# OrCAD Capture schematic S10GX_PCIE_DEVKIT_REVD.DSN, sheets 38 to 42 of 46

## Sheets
38 Power - VCCRAM: size C
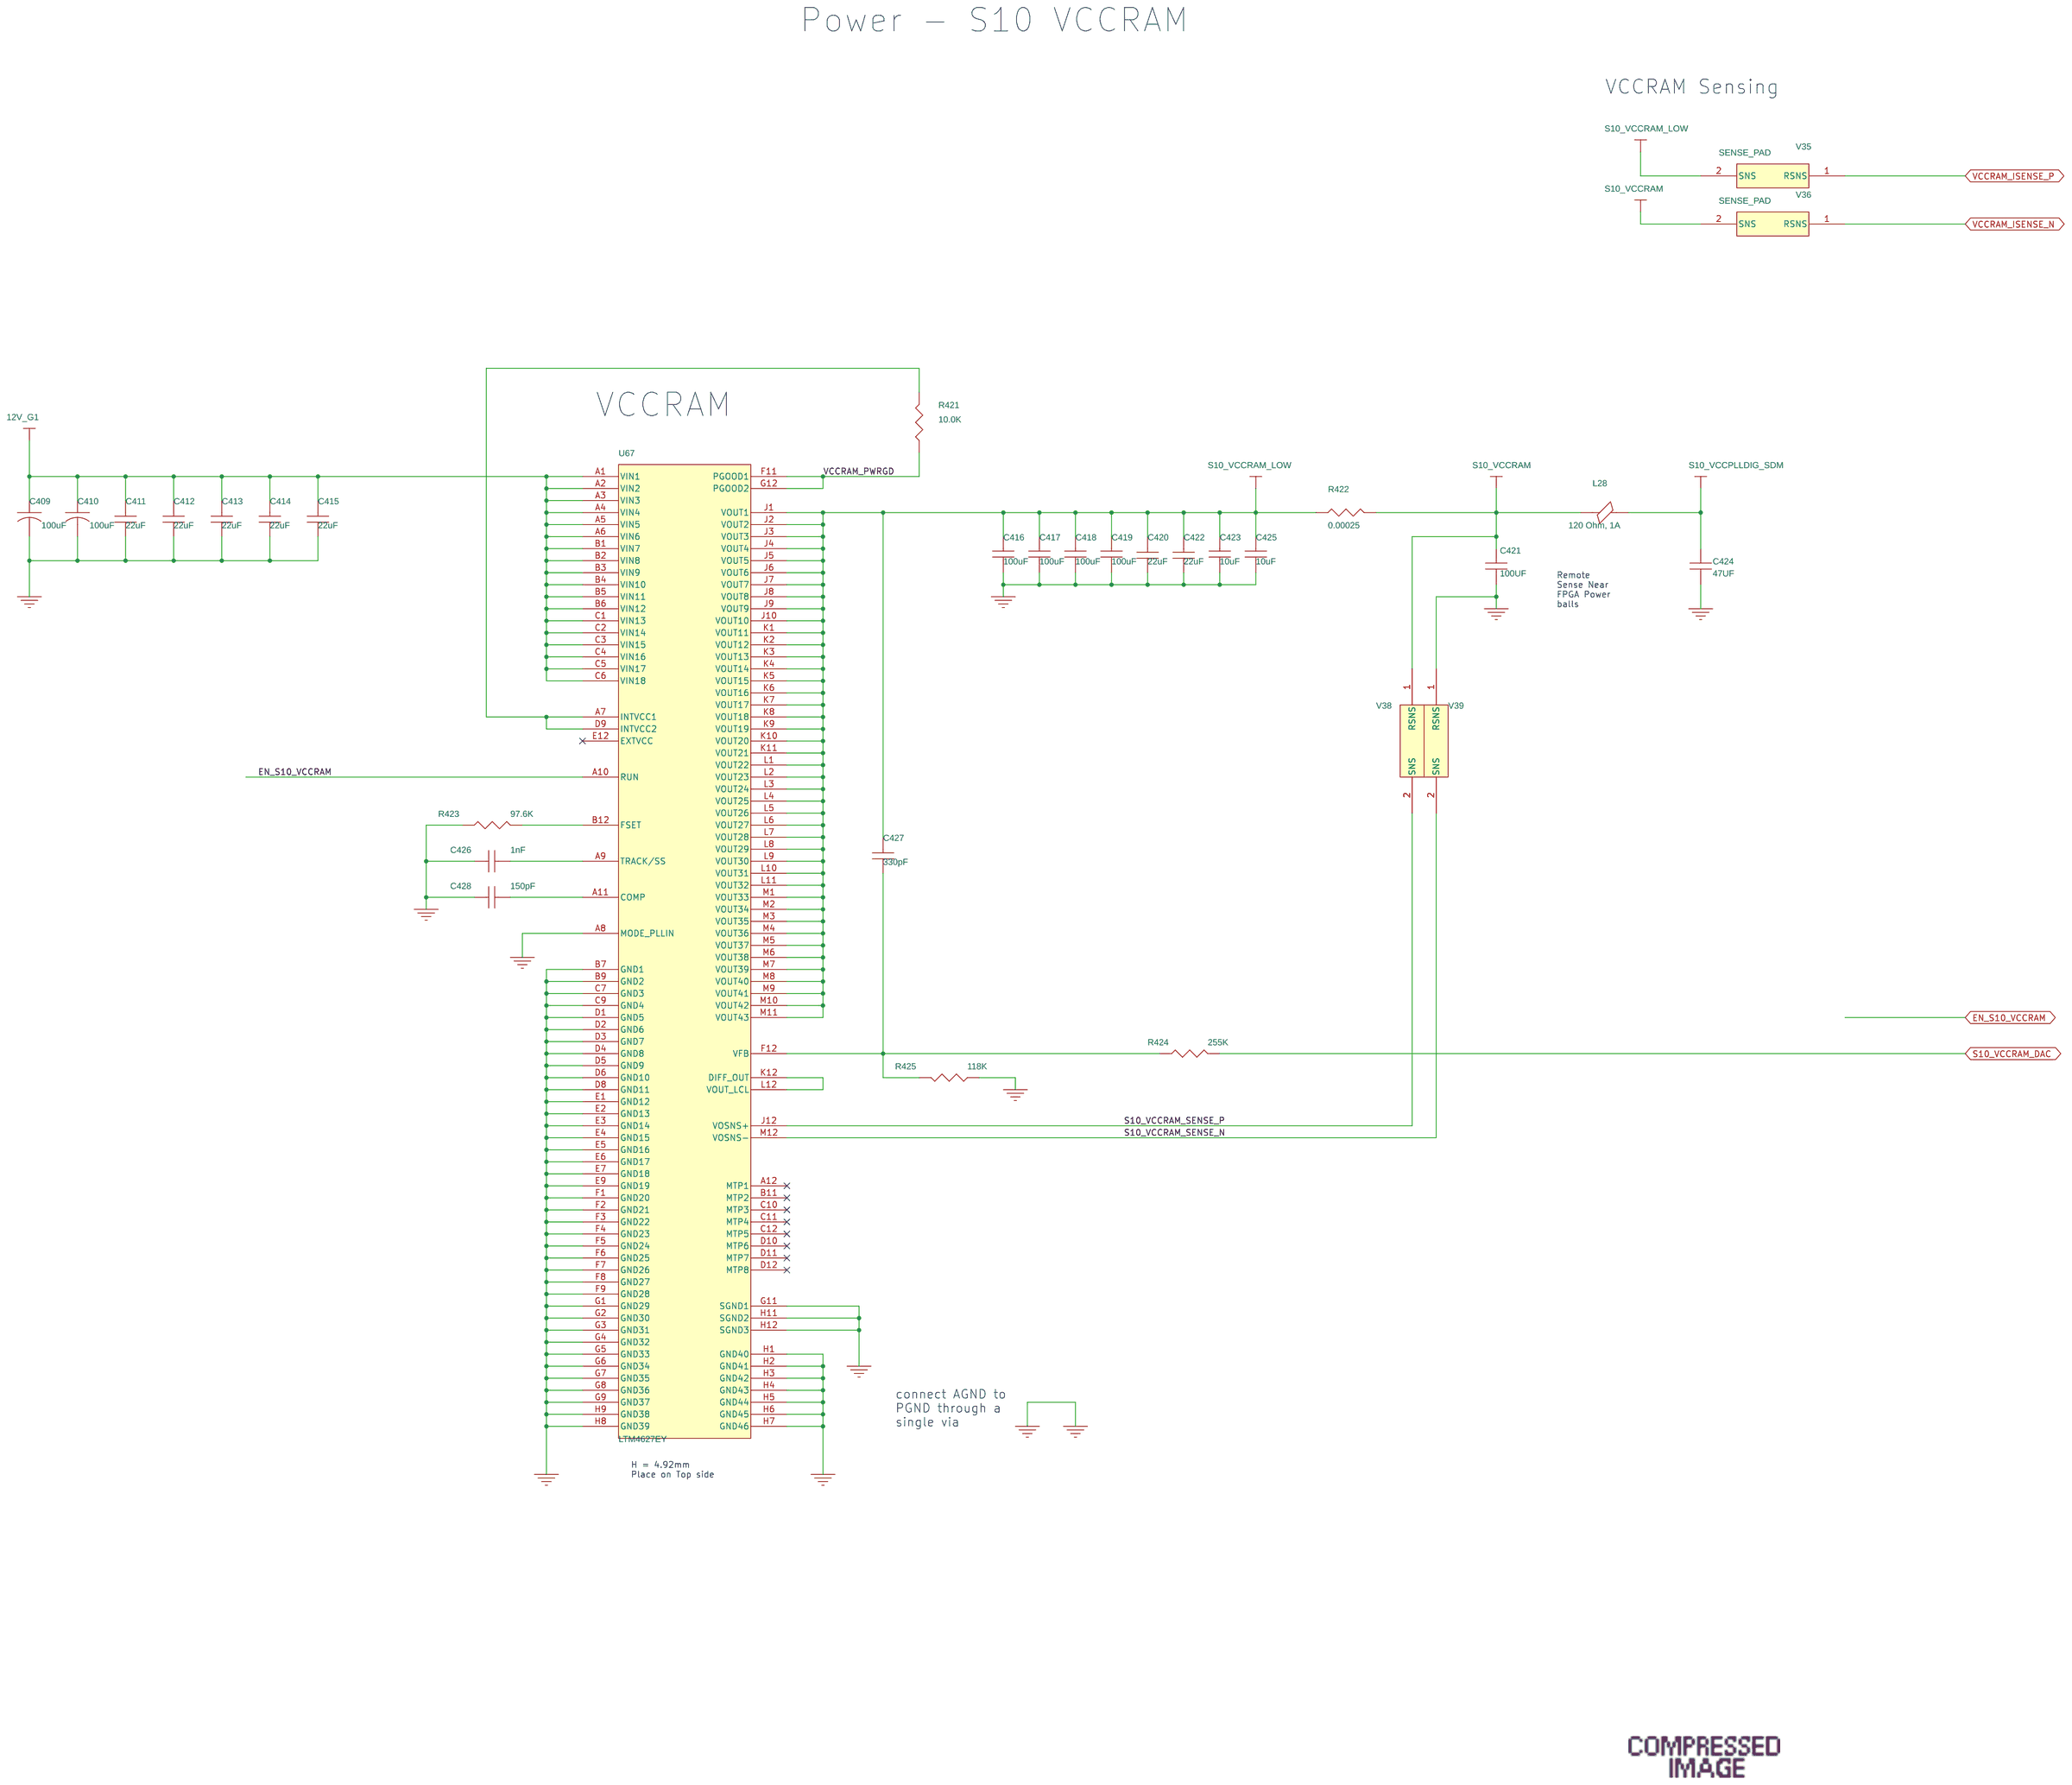
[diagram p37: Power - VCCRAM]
39 Power - VCCPT & 1.8V: size C
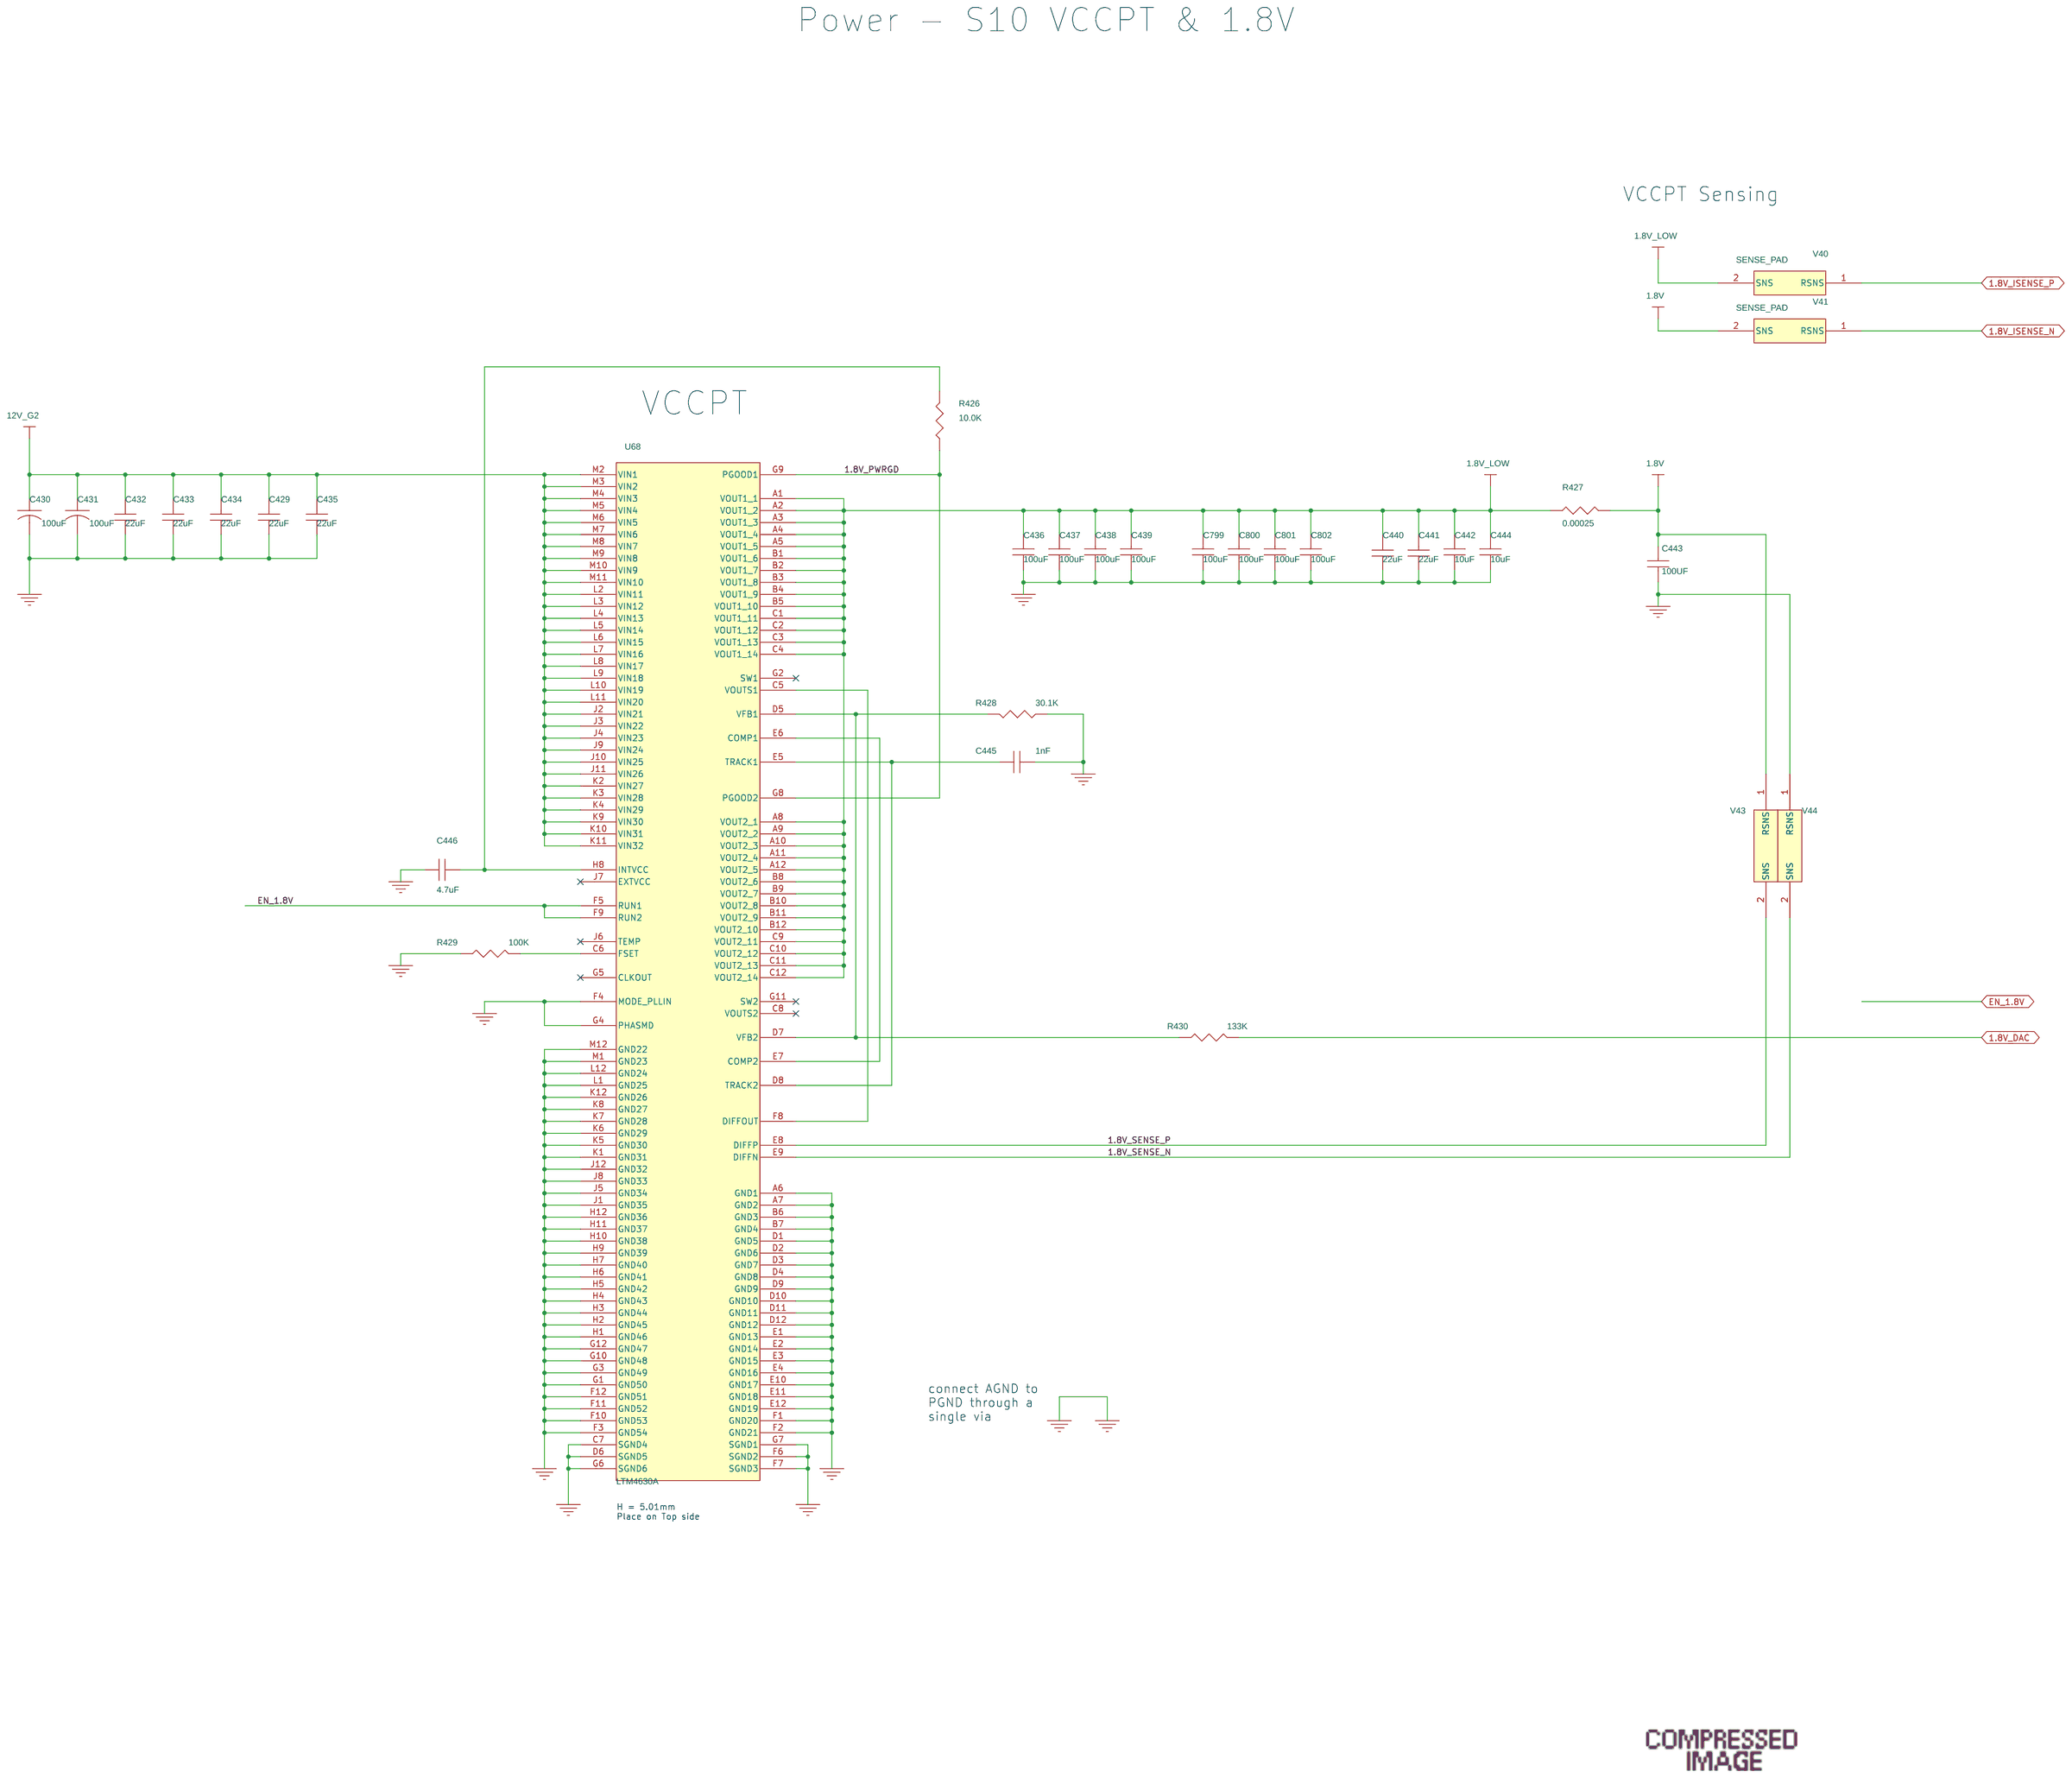
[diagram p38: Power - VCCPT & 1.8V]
40 Power - VCCR_GXB, VCCT_GXB: size C
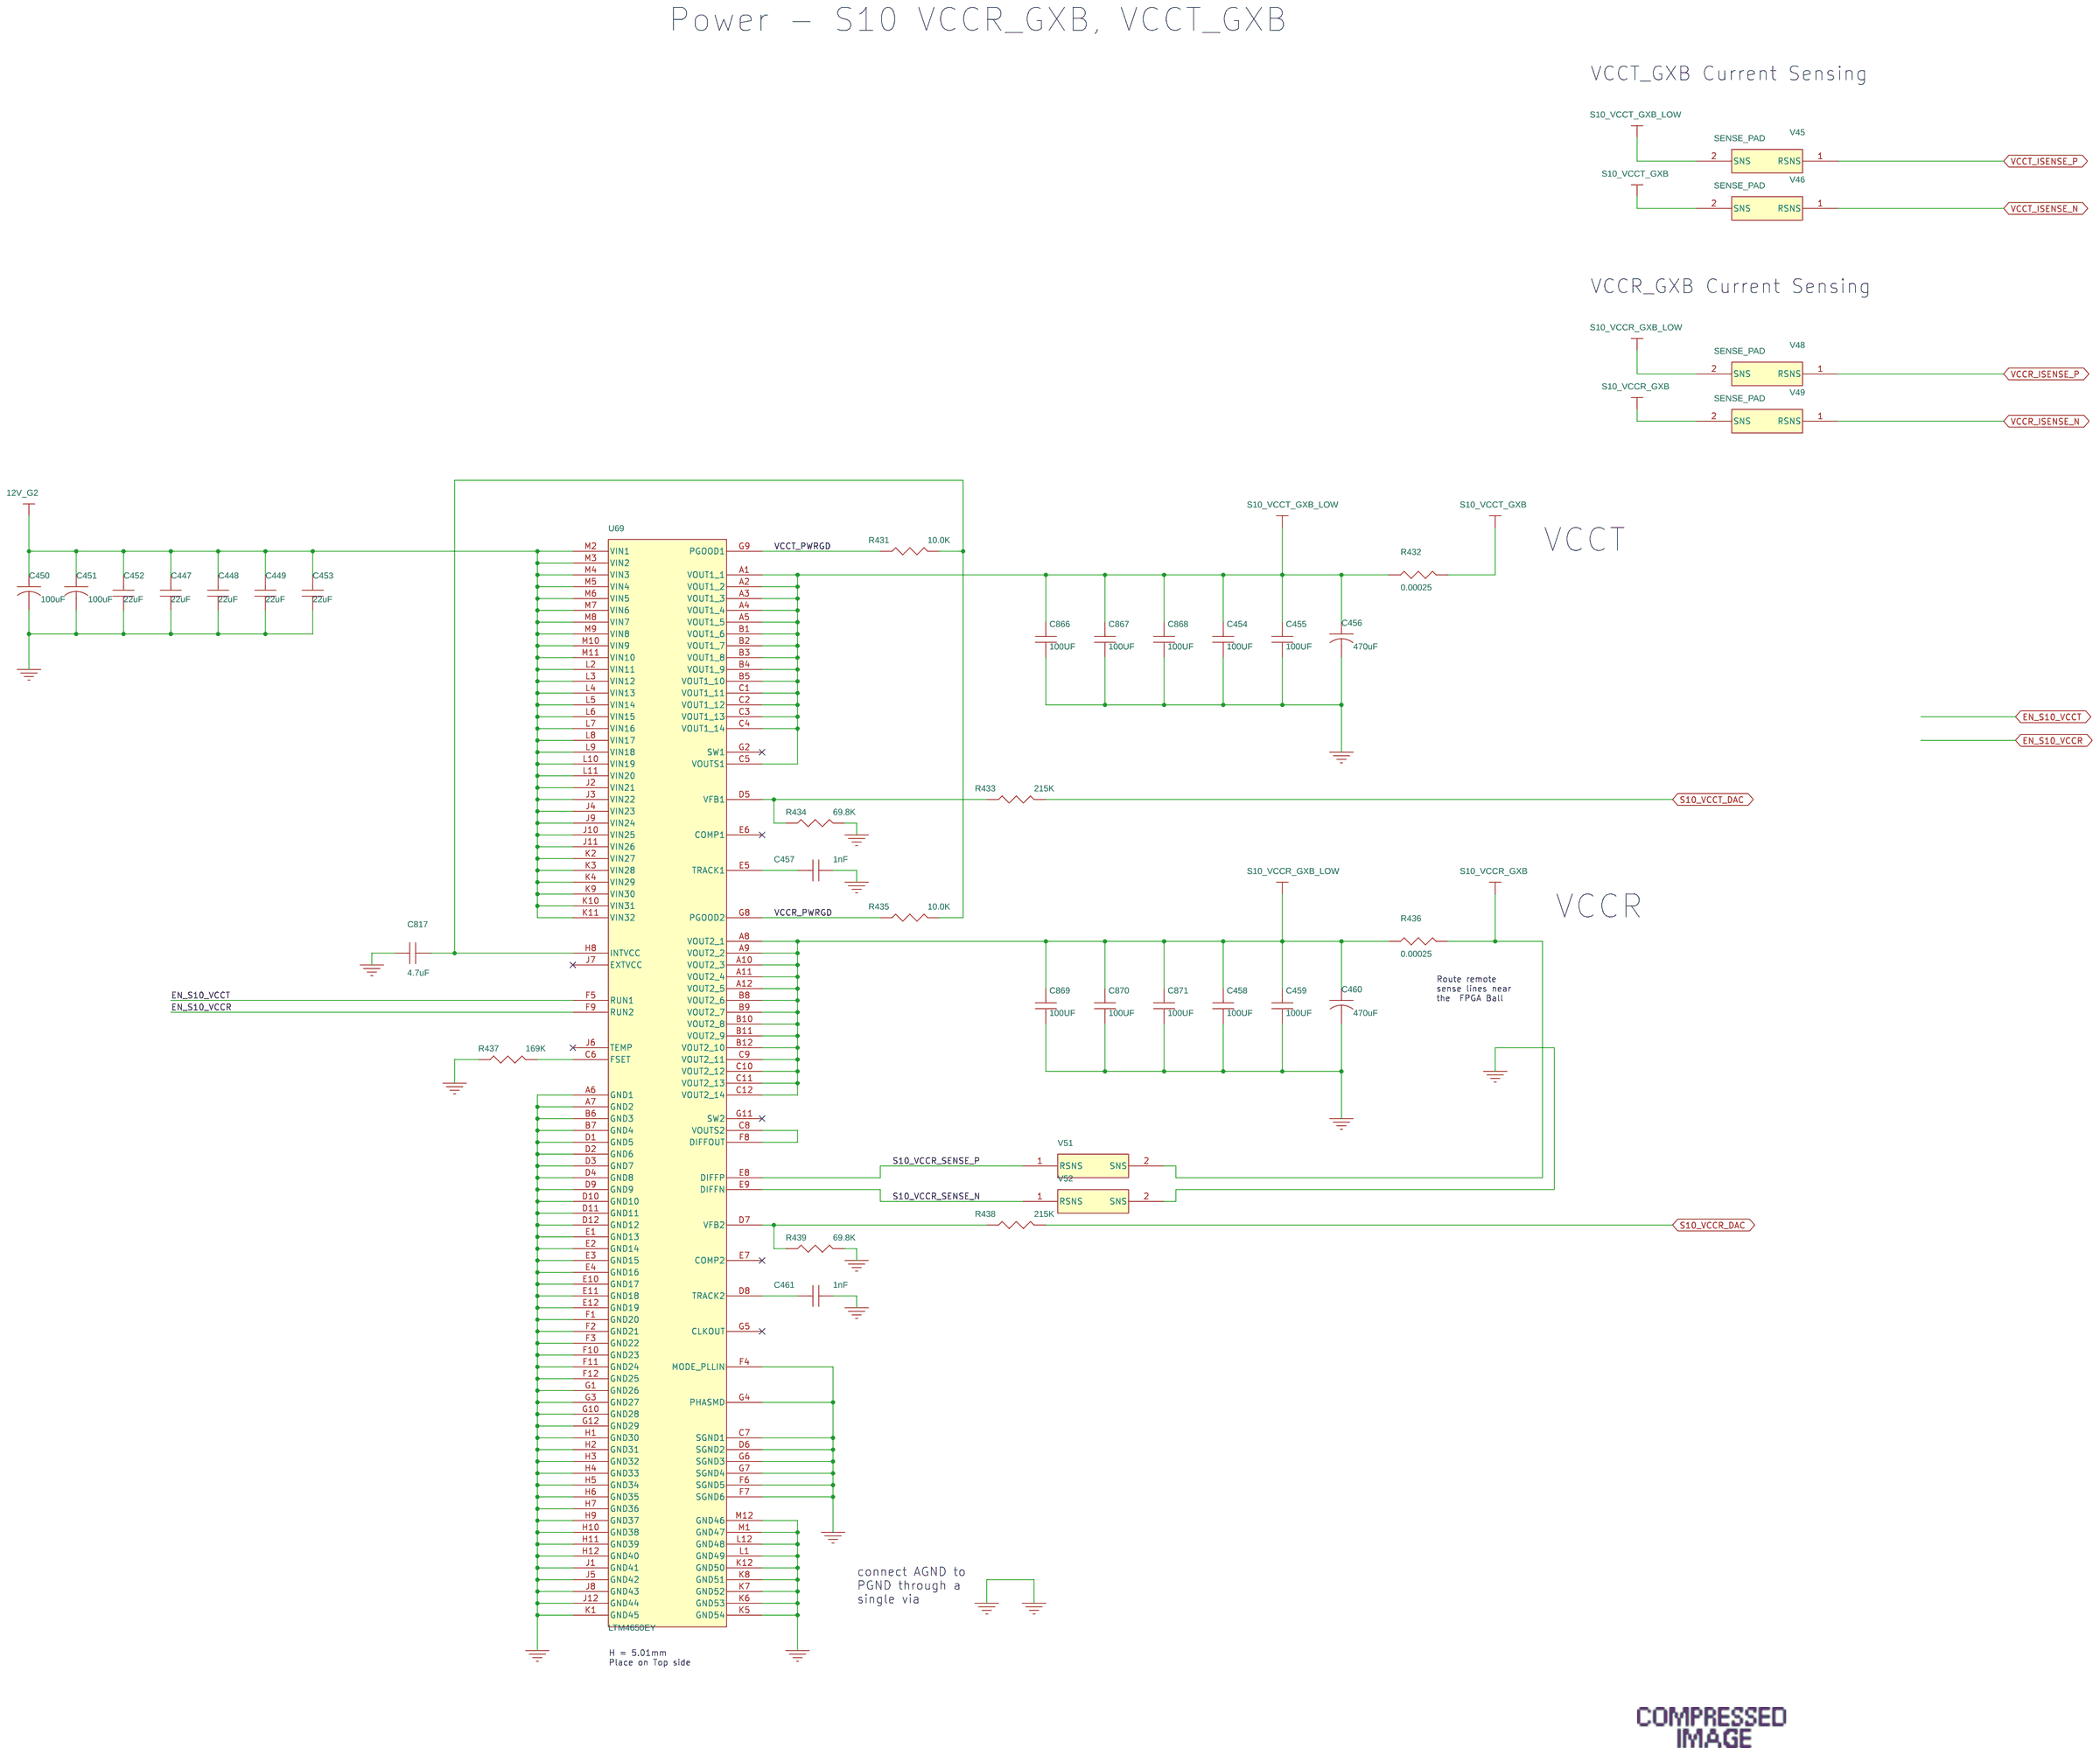
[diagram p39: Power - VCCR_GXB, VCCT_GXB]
41 Power - FMC: size C
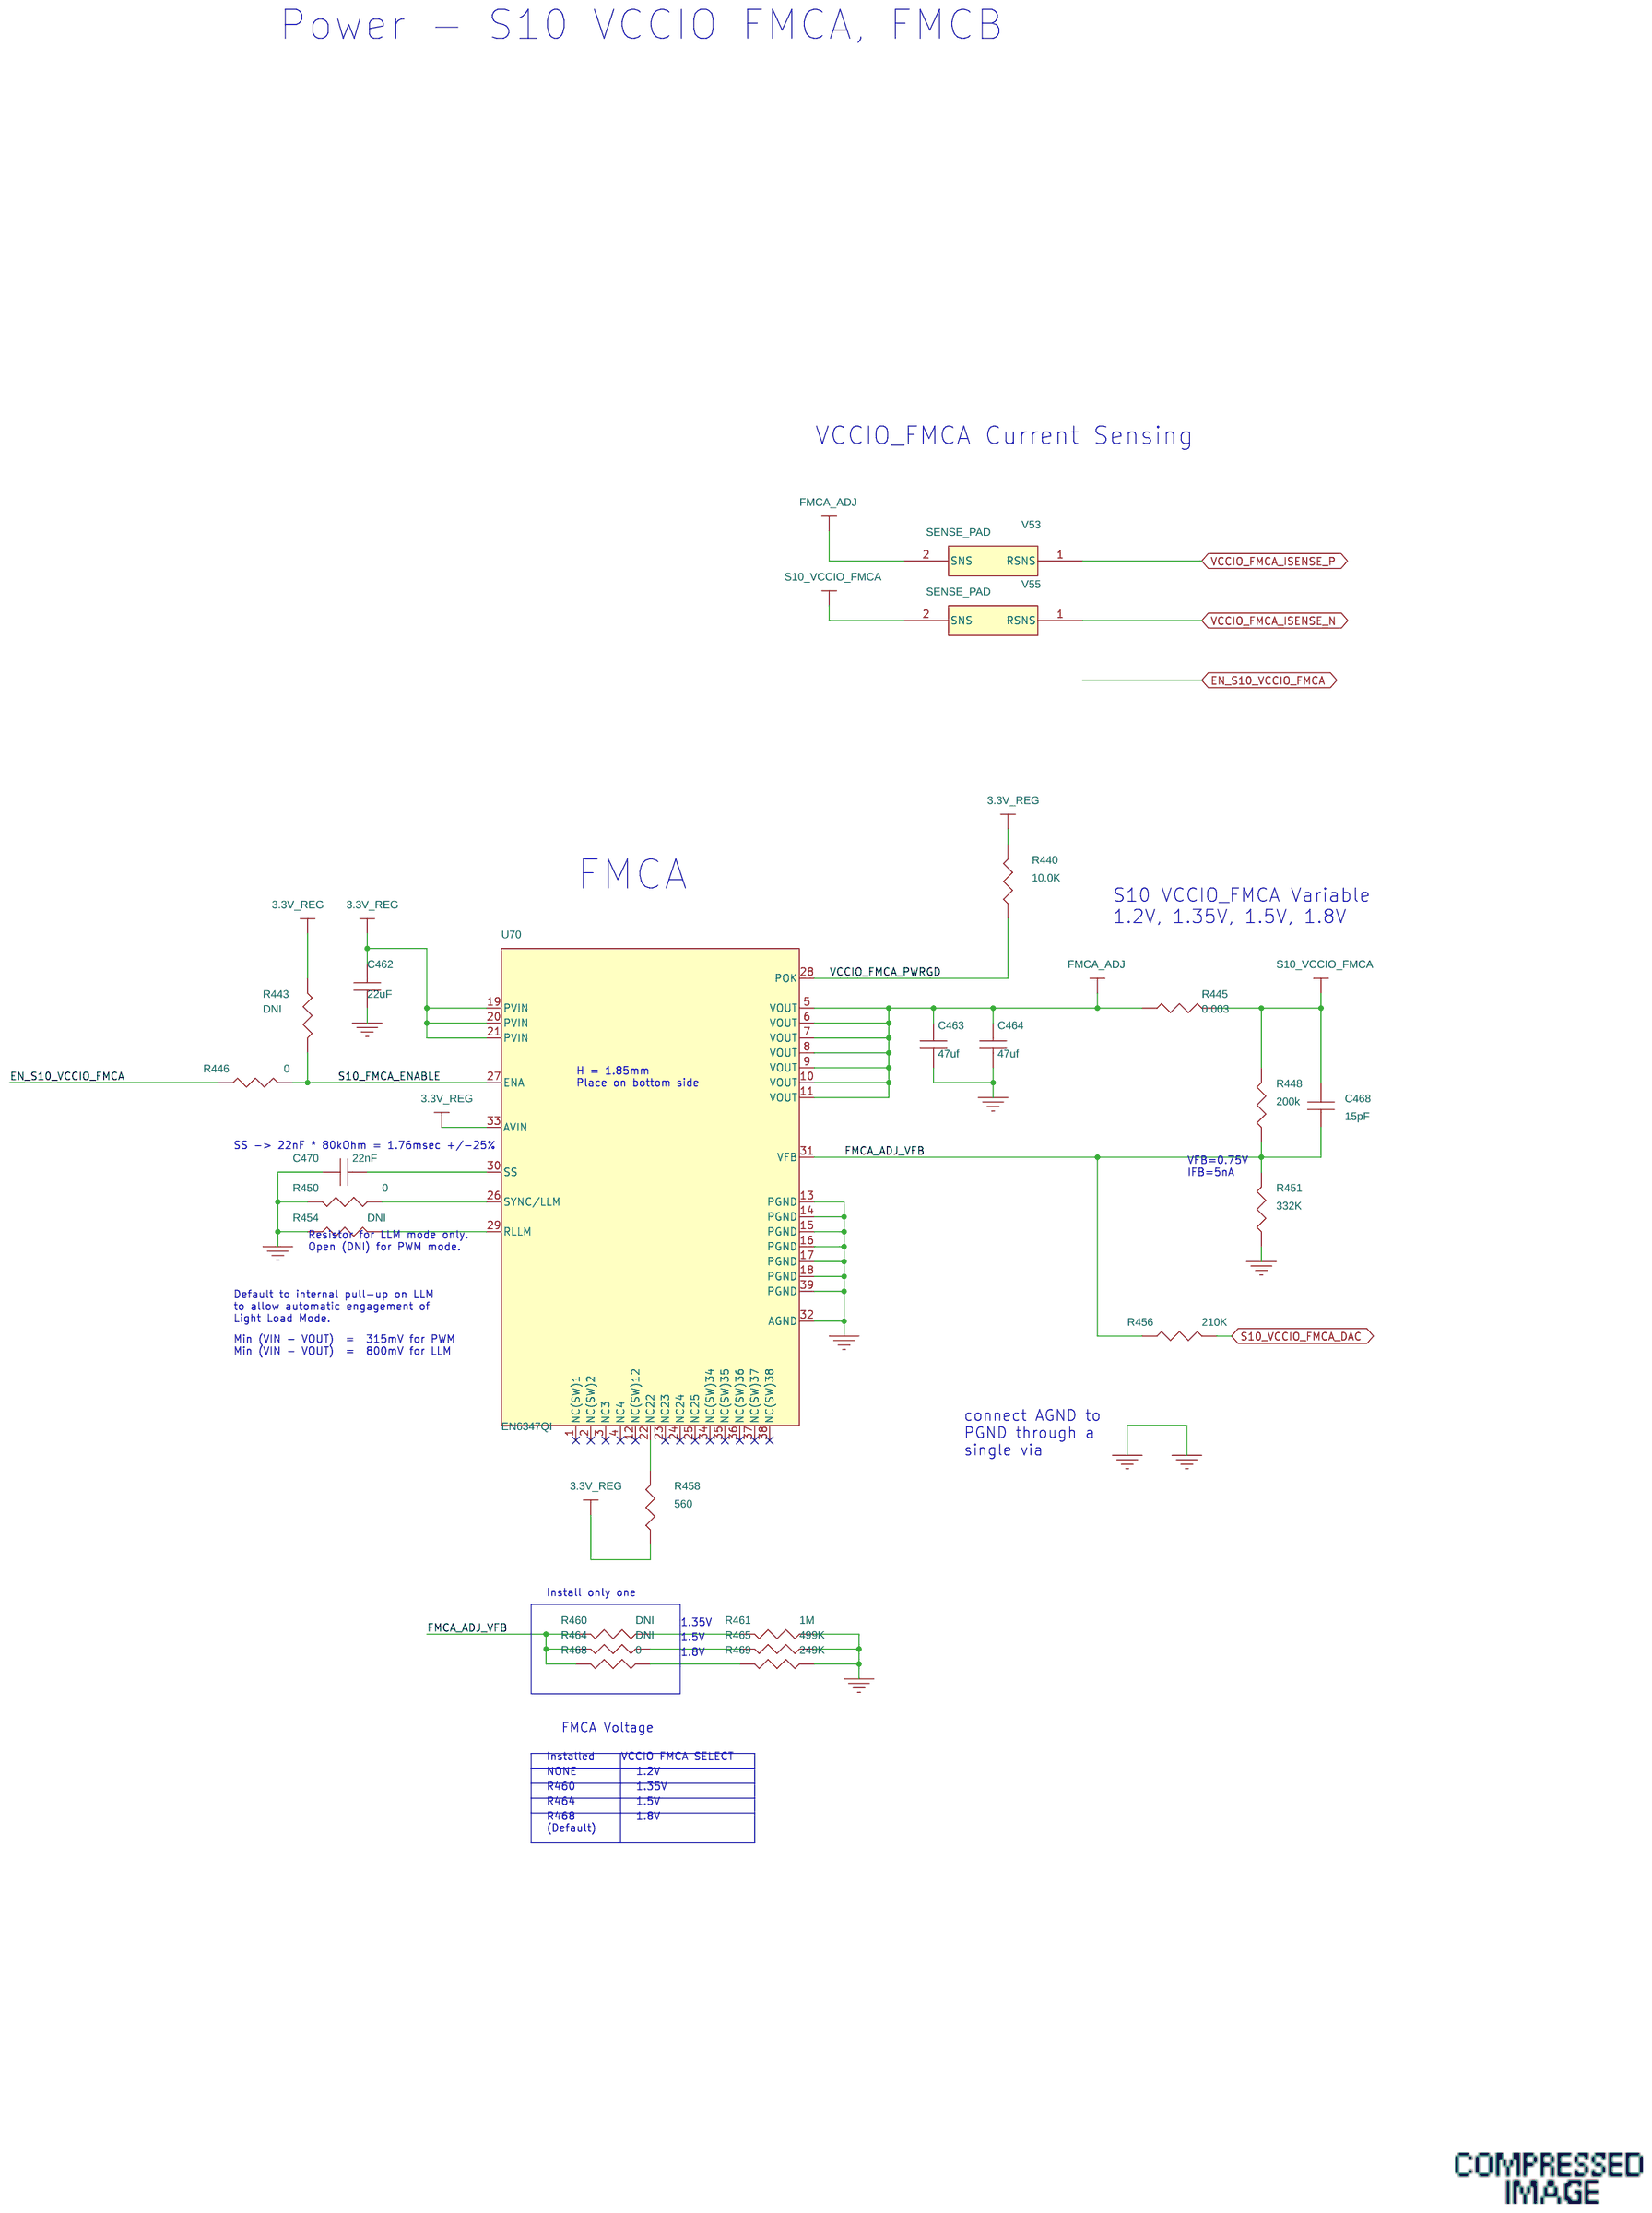
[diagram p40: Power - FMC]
42 Power - HILO MEMORY: size C
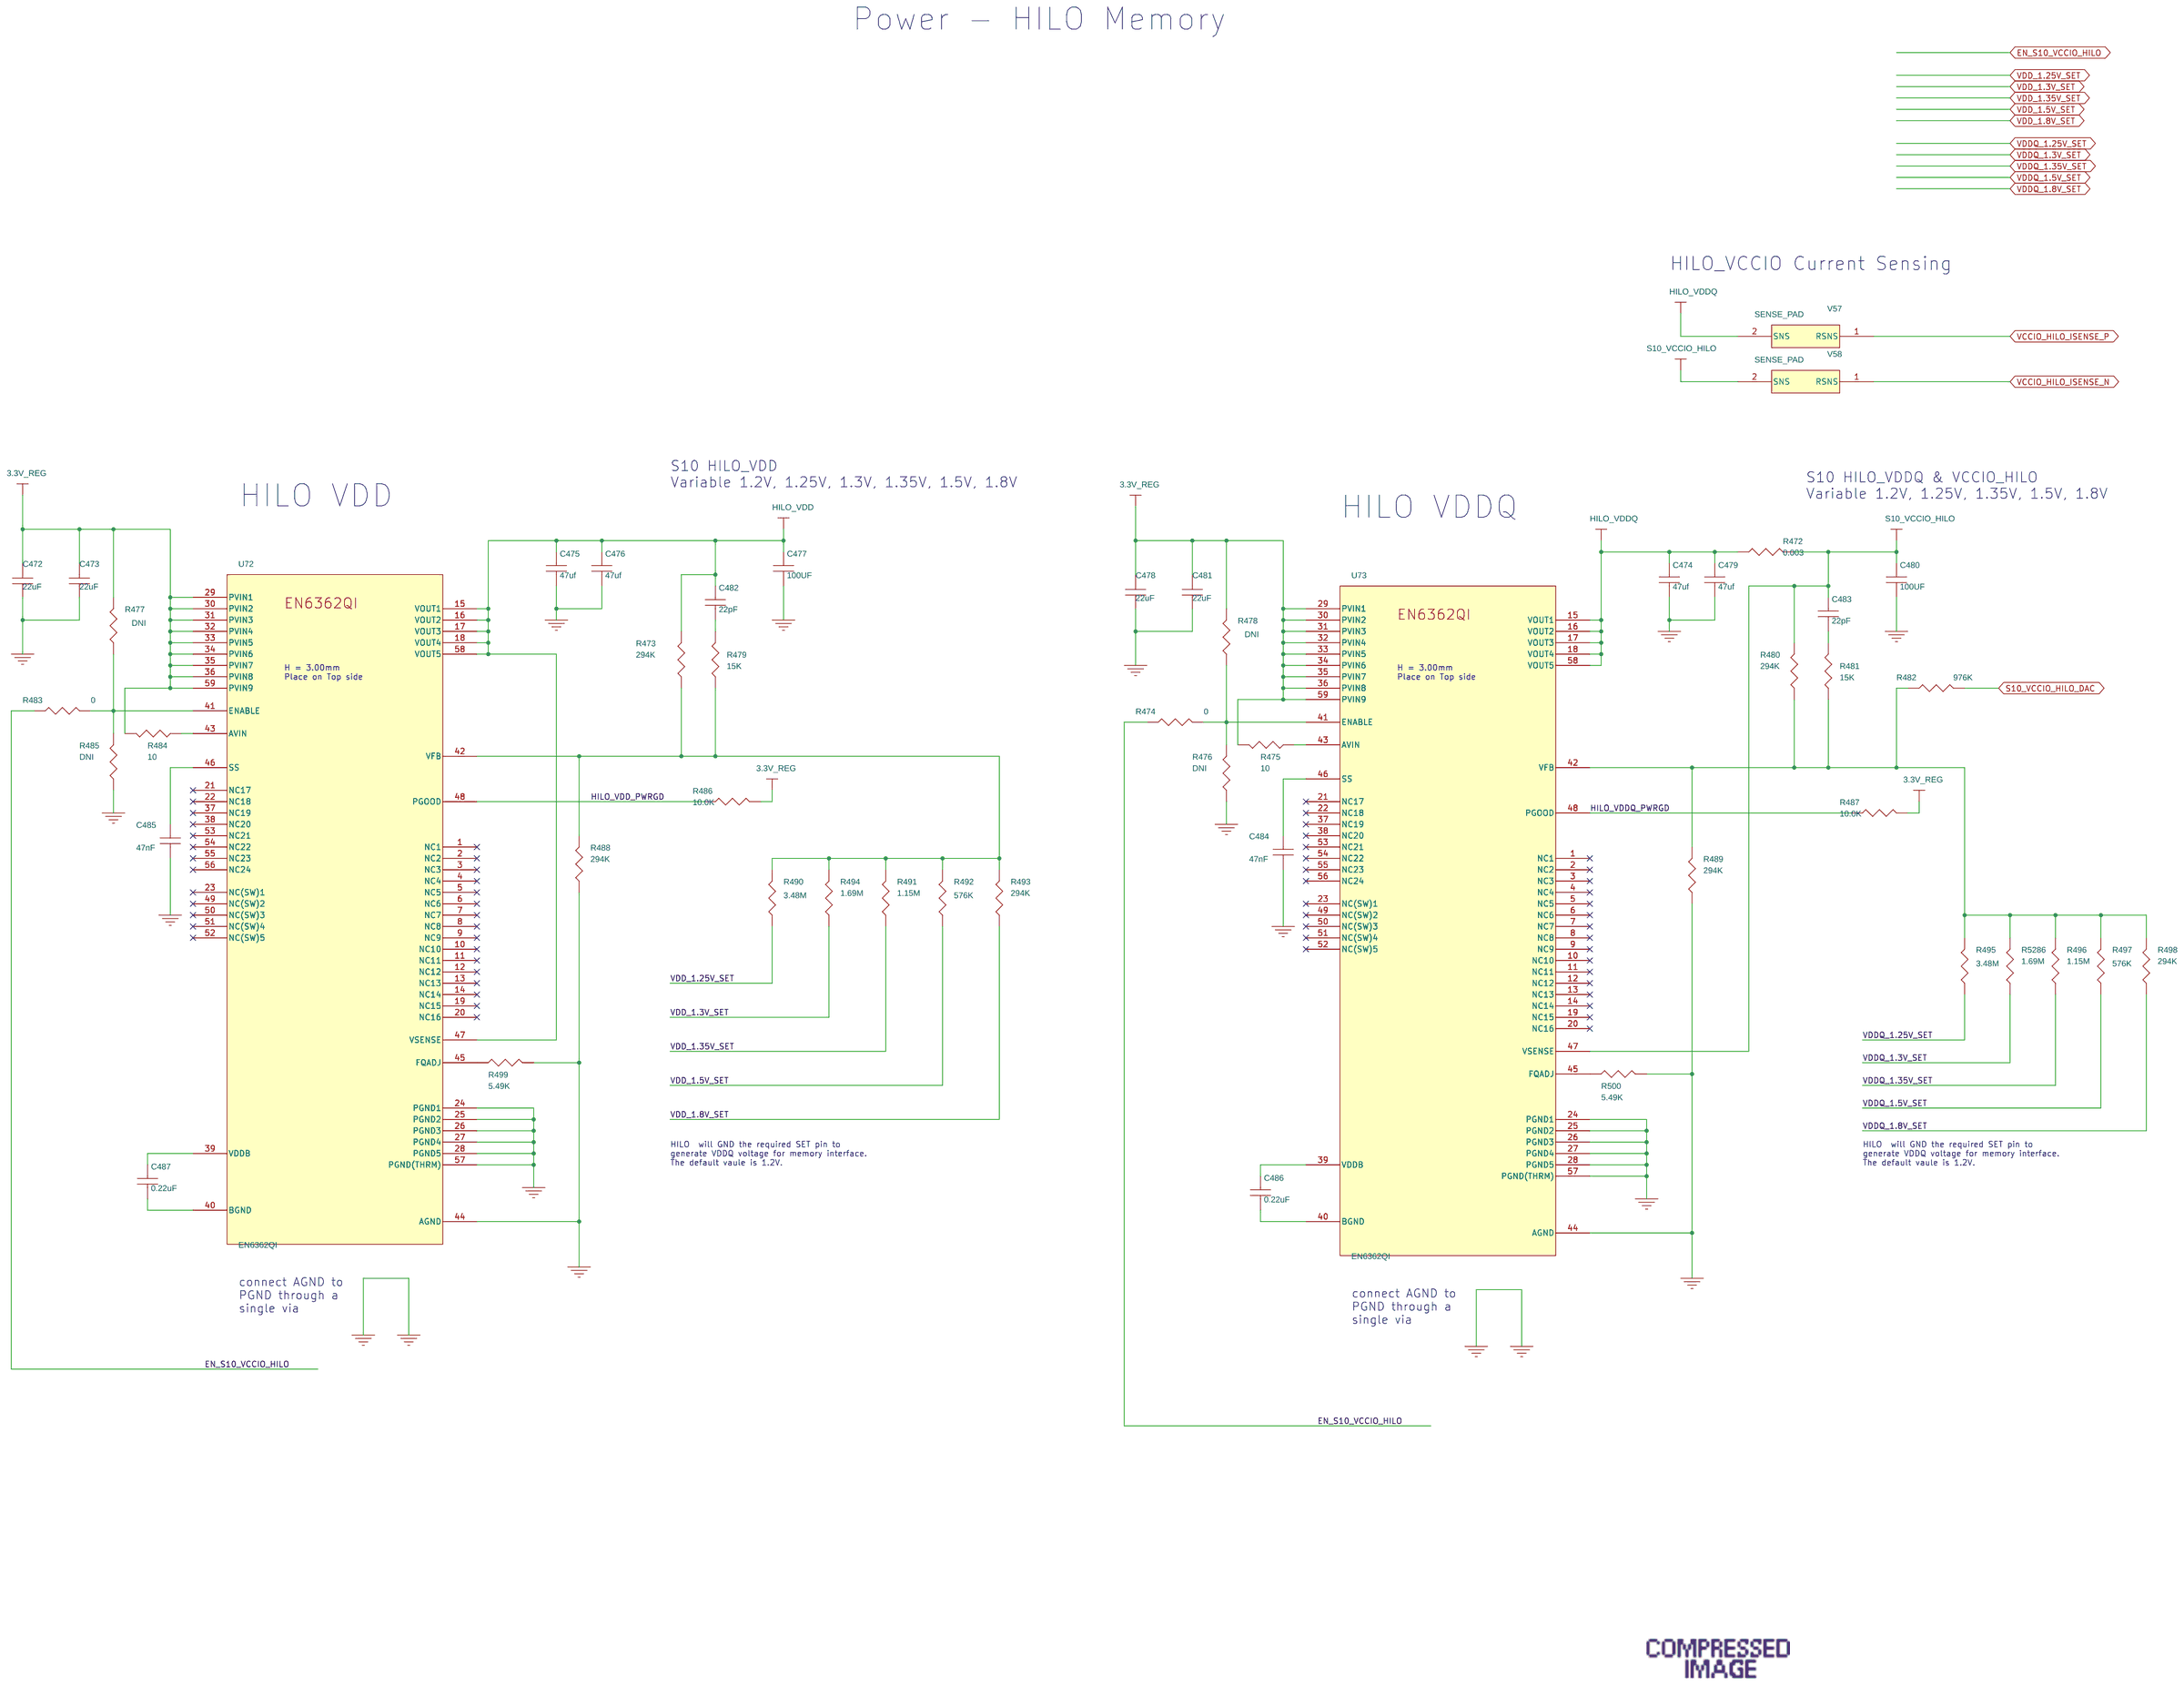
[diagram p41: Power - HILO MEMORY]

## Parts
sheet Power - FMC
C462  22uF  [1206]
C463  47uf  [1206]
C464  47uf  [1206]
C468  15pF  [0402]
C470  22nF  [0402]
R440  10.0K  [0402]
R443  DNI  [0402]
R445  0.003  [WSL2010]
R446  0  [0402]
R448  200k  [0402]
R450  0  [0402]
R451  332K  [0402]
R454  DNI  [0402]
R456  210K  [0402]
R458  560  [0402]
R460  DNI  [0805]
R461  1M  [0402]
R464  DNI  [0805]
R465  499K  [0402]
R468  0  [0805]
R469  249K  [0402]
U70  EN6347QI  [QFN38]
V53  SENSE_PAD  [SENSE]
V55  SENSE_PAD  [SENSE]
sheet Power - HILO MEMORY
C472  22uF  [1206]
C473  22uF  [1206]
C474  47uf  [1206]
C475  47uf  [1206]
C476  47uf  [1206]
C477  100UF  [1206]
C478  22uF  [1206]
C479  47uf  [1206]
C480  100UF  [1206]
C481  22uF  [1206]
C482  22pF  [0402]
C483  22pF  [0402]
C484  47nF  [0402]
C485  47nF  [0402]
C486  0.22uF  [0402]
C487  0.22uF  [0402]
R472  0.003  [WSL2010]
R473  294K  [0402]
R474  0  [0402]
R475  10  [0402]
R476  DNI  [0402]
R477  DNI  [0402]
R478  DNI  [0402]
R479  15K  [0402]
R480  294K  [0402]
R481  15K  [0402]
R482  976K  [0402]
R483  0  [0402]
R484  10  [0402]
R485  DNI  [0402]
R486  10.0K  [0402]
R487  10.0K  [0402]
R488  294K  [0402]
R489  294K  [0402]
R490  3.48M  [0402]
R491  1.15M  [0402]
R492  576K  [0402]
R493  294K  [0402]
R494  1.69M  [0402]
R495  3.48M  [0402]
R496  1.15M  [0402]
R497  576K  [0402]
R498  294K  [0402]
R499  5.49K  [0402]
R500  5.49K  [0402]
R5286  1.69M  [0402]
U72  EN6362QI  [QFN-56_EN6362QI]
U73  EN6362QI  [QFN-56_EN6362QI]
V57  SENSE_PAD  [SENSE]
V58  SENSE_PAD  [SENSE]
sheet Power - VCCPT & 1.8V
C429  22uF  [1206]
C430  100uF  [7343-V_low-profile]
C431  100uF  [7343-V_low-profile]
C432  22uF  [1206]
C433  22uF  [1206]
C434  22uF  [1206]
C435  22uF  [1206]
C436  100uF  [1206]
C437  100uF  [1206]
C438  100uF  [1206]
C439  100uF  [1206]
C440  22uF  [1206]
C441  22uF  [1206]
C442  10uF  [0603]
C443  100UF  [1206]
C444  10uF  [0603]
C445  1nF  [0402]
C446  4.7uF  [0402]
C799  100uF  [1206]
C800  100uF  [1206]
C801  100uF  [1206]
C802  100uF  [1206]
R426  10.0K  [0402]
R427  0.00025  [CSS2725]
R428  30.1K  [0402]
R429  100K  [0402]
R430  133K  [0402]
U68  LTM4630A  [GBA_LGA-144_REVERSE]
V40  SENSE_PAD  [SENSE]
V41  SENSE_PAD  [SENSE]
V43  SENSE_PAD  [SENSE]
V44  SENSE_PAD  [SENSE]
sheet Power - VCCR_GXB, VCCT_GXB
C447  22uF  [1206]
C448  22uF  [1206]
C449  22uF  [1206]
C450  100uF  [7343-V_low-profile]
C451  100uF  [7343-V_low-profile]
C452  22uF  [1206]
C453  22uF  [1206]
C454  100UF  [1206]
C455  100UF  [1206]
C456  470uF  [7343]
C457  1nF  [0402]
C458  100UF  [1206]
C459  100UF  [1206]
C460  470uF  [7343]
C461  1nF  [0402]
C817  4.7uF  [0402]
C866  100UF  [1206]
C867  100UF  [1206]
C868  100UF  [1206]
C869  100UF  [1206]
C870  100UF  [1206]
C871  100UF  [1206]
R431  10.0K  [0402]
R432  0.00025  [CSS2725]
R433  215K  [0402]
R434  69.8K  [0402]
R435  10.0K  [0402]
R436  0.00025  [CSS2725]
R437  169K  [0402]
R438  215K  [0402]
R439  69.8K  [0402]
U69  LTM4650EY  [BGA-144_REVERSE]
V45  SENSE_PAD  [SENSE]
V46  SENSE_PAD  [SENSE]
V48  SENSE_PAD  [SENSE]
V49  SENSE_PAD  [SENSE]
V51  SENSE_PAD  [SENSE]
V52  SENSE_PAD  [SENSE]
sheet Power - VCCRAM
C409  100uF  [7343-V_low-profile]
C410  100uF  [7343-V_low-profile]
C411  22uF  [1206]
C412  22uF  [1206]
C413  22uF  [1206]
C414  22uF  [1206]
C415  22uF  [1206]
C416  100uF  [1206]
C417  100uF  [1206]
C418  100uF  [1206]
C419  100uF  [1206]
C420  22uF  [1206]
C421  100UF  [1206]
C422  22uF  [1206]
C423  10uF  [0603]
C424  47UF  [0805]
C425  10uF  [0603]
C426  1nF  [0402]
C427  330pF  [0603]
C428  150pF  [0402]
L28  120 Ohm, 1A  [0402]
R421  10.0K  [0402]
R422  0.00025  [CSS2725]
R423  97.6K  [0402]
R424  255K  [0402]
R425  118K  [0402]
U67  LTM4627EY  [BGA-133]
V35  SENSE_PAD  [SENSE]
V36  SENSE_PAD  [SENSE]
V38  SENSE_PAD  [SENSE]
V39  SENSE_PAD  [SENSE]

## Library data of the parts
C411-C415 C420 C422 C429 C432-C435 C440 C441 C447-C449 C452 C453 C462 C472 C473 C478 C481 = CAP: CAP - CER, 22UF, 25V, 10%, X5R, 1206; Item Num: P03-17640R; Lead Free Status: Yes; Manufacturer: Murata; Manufacturer Part Num: GRM31CR61E226KE15L; Num Pins: 2; Part Class: Capacitors; Price: 0; RoHS Compliant: Yes
C463 C464 C474-C476 C479 = CAP: CAP -   CER, 47UF, 10V, 20%, X5R, 1206, SMD; AGILE_LINK: http://sj-agile9app/Agile/PLMServlet?action=OpenEmailObject&classid=10000&objid=146494148; CAPACITANCE: 47uF; Item Num: P03-17650R; LIFECYCLE_PHASE: Active; MFR_LIFECYCLE: Active; Manufacturer: Taiyo Yuden; Manufacturer Part Num: LMK316BJ476ML-T; Num Pins: 2; PART_SUBCLASS: CAPACITORS; RATED_VOLTAGE: 10V; RoHS Compliant: RoHS Compliant; TOLERANCE: +/-20%
C468 = CAP: CAP - CER ,15PF, 50V, 5%, C0G, 0402; Item Num: P03-15372R; Lead Free Status: Yes; Manufacturer: Murata; Manufacturer Part Num: GRM1555C1H150JZ01D; Num Pins: 2; Part Class: Capacitors; Price: 0; RoHS Compliant: Yes
C470 = CAP: CAP - CER, 22NF, 25V, +/-10%, X7R, 0402 SMD; AGILE_LINK: http://sj-agile9app/Agile/PLMServlet?action=OpenEmailObject&classid=10000&objid=256989767; CAPACITANCE: 22000pF; Item Num: P03-16317R; LIFECYCLE_PHASE: Active; Lead Free Status: Lead Free; MFR_LIFECYCLE: Active; Manufacturer: Murata; Manufacturer Part Num: GRM155R71E223KA61D; Num Pins: 2; PART_SUBCLASS: CAPACITORS; RATED_VOLTAGE: 25V; RoHS Compliant: RoHS Compliant; TOLERANCE: +80%/-20%
R440 R486 R487 = RESISTOR: RES,10.0K OHMS,1.0%,1/16W, 0402; AGILE_LINK: http://sj-agile9app/Agile/PLMServlet?action=OpenEmailObject&classid=10000&objid=146548997; Item Num: P02-11364R; LIFECYCLE_PHASE: Active; Lead Free Status: No; MFR_LIFECYCLE: Active; Manufacturer: Panasonic; Manufacturer Part Num: ERJ-2RKF1002X; Num Pins: 2; PART_SUBCLASS: RESISTORS; POWER: 1/16W; RoHS Compliant: Yes; TOLERANCE: +/-1%
R443 R454 = RESISTOR: RES,10.0K OHMS,1.0%,1/16W, 0402; AGILE_LINK: http://sj-agile9app/Agile/PLMServlet?action=OpenEmailObject&classid=10000&objid=146548997; Item Num: P02-11364R; LIFECYCLE_PHASE: Active; Lead Free Status: No; MFR_LIFECYCLE: Active; Manufacturer: Panasonic; Manufacturer Part Num: ERJ-2RKF1002X; Num Pins: 2; PART_SUBCLASS: RESISTORS; POWER: 1/16W; RESISTANCE: 10.0K; RoHS Compliant: Yes; TOLERANCE: +/-1%
R445 R472 = RESISTOR: RES, 0.003 OHM, 1%, 1/2W, POWERMETAL; AGILE_LINK: http://sj-agile9app/Agile/PLMServlet?action=OpenEmailObject&classid=10000&objid=112752009; Item Num: P02-10702R; LIFECYCLE_PHASE: Active; Lead Free Status: Yes; Manufacturer: Vishay; Manufacturer Part Num: WSL20103L000FEA; Num Pins: 2; PART_SUBCLASS: RESISTORS; POWER: 1/2W; TOLERANCE: +/-1%
R446 R450 = RESISTOR: RES ZERO OHM 1/16W 5% 0402 SMD; Altera Part No.: P02-14020R; Item Num: P02-14020R; Lead Free Status: No; Manufacturer: Panasonic; Manufacturer Part Num: ERJ-2GE0R00X; Num Pins: 2; Part Class: RESISTORS; RoHS Compliant: Yes; Tolerance: 5%
R448 = RES: RES - 200K OHM, 1/16W, 1%, 0402 SMD; Item Num: P02-15992R; Manufacturer: Panasonic; Manufacturer Part Num: ERJ-2RKF2003X; Package: SMD; Part Class: RESISTORS; Type: Resistor
R451 = RESISTOR: 332K OHM, 1/10W, 1%, 0402 SMD; Item Num: P02-17519R; Lead Free Status: No; Manufacturer: Panasonic; Manufacturer Part Num: ERJ-2RKF3323X; Num Pins: 2; Part Class: Resistors; Price: 0; RoHS Compliant: Yes
R456 = RESISTOR: RES 210K OHM 1/10W 1% 0402 SMD; Item Num: P02-17571R; Lead Free Status: No; Manufacturer: Panasonic; Manufacturer Part Num: ERJ-S02F2103X; Num Pins: 2; Part Class: RESISTORS; Price: 0; RoHS Compliant: Yes; Tolerance: 1%
R458 = RESISTOR: RES, 560 OHM, 5%, 1/16W, 0402, SMD; Item Num: P02-14928R; Lead Free Status: Yes; Manufacturer: Panasonic; Manufacturer Part Num: ERJ-2GEJ561x; Num Pins: 2; Part Class: RESISTORS; Price: 0; RoHS Compliant: Yes
R460 R464 = RESISTOR: RES SMD 0.0 OHM JUMPER 1/8W 0805; AGILE_LINK: http://sj-agile9app/Agile/PLMServlet?action=OpenEmailObject&classid=10000&objid=258802890; Item Num: P02-XXXXXR; LIFECYCLE_PHASE: Active; Lead Free Status: Lead Free; MFR_LIFECYCLE: Active; Manufacturer: Bourns Inc; Manufacturer Part Num: CR0805-J/-000ELF; Num Pins: 2; PART_SUBCLASS: RESISTORS; POWER: 1/8W; RoHS Compliant: RoHS Compliant; TOLERANCE: +/-1%
R461 = RESISTOR: RES 1.00M OHM 1/16W 1% 0402 SMD; AGILE_LINK: http://sj-agile9app/Agile/PLMServlet?action=OpenEmailObject&classid=10000&objid=258802890; Item Num: P02-14034R; LIFECYCLE_PHASE: Active; Lead Free Status: Lead Free; MFR_LIFECYCLE: Active; Manufacturer: Panasonic; Manufacturer Part Num: ERJ-2RKF1004X; Num Pins: 2; PART_SUBCLASS: RESISTORS; POWER: 1/16W; RoHS Compliant: RoHS Compliant; TOLERANCE: +/-1%
R465 = RESISTOR: RES, 499K OHM,1%, 1/16W, 0402, SMD; AGILE_LINK: http://sj-agile9app/Agile/PLMServlet?action=OpenEmailObject&classid=10000&objid=258802890; Item Num: P02-14134R; LIFECYCLE_PHASE: Active; Lead Free Status: Lead Free; MFR_LIFECYCLE: Active; Manufacturer: Panasonic; Manufacturer Part Num: ERJ-2RKF4993X; Num Pins: 2; PART_SUBCLASS: RESISTORS; POWER: 1/10W; RoHS Compliant: RoHS Compliant; TOLERANCE: +/-1%
R468 = RESISTOR: RES SMD 0.0 OHM JUMPER 1/8W 0805; AGILE_LINK: http://sj-agile9app/Agile/PLMServlet?action=OpenEmailObject&classid=10000&objid=258802890; Item Num: P02-17731R; LIFECYCLE_PHASE: Active; Lead Free Status: Lead Free; MFR_LIFECYCLE: Active; Manufacturer: Bourns Inc; Manufacturer Part Num: CR0805-J/-000ELF; Num Pins: 2; PART_SUBCLASS: RESISTORS; POWER: 1/8W; RoHS Compliant: RoHS Compliant; TOLERANCE: +/-1%
R469 = RESISTOR: RES - 249K OHM, 1/16W, 1%, 0402 SMD; AGILE_LINK: http://sj-agile9app/Agile/PLMServlet?action=OpenEmailObject&classid=10000&objid=258802890; Item Num: P02-16449R; LIFECYCLE_PHASE: Active; Lead Free Status: Lead Free; MFR_LIFECYCLE: Active; Manufacturer: Panasonic; Manufacturer Part Num: ERJ-2RKF2493X; Num Pins: 2; PART_SUBCLASS: RESISTORS; POWER: 1/16W; RoHS Compliant: RoHS Compliant; TOLERANCE: +/-1%
U70 = EN6347: IC, VREG, BUCK, 2.5V-6.6V VIN, 4A, EN6347QI; Item Num: P01-17990R; Manufacturer: Enpirion
V35 V36 V38-V41 V43-V46 V48 V49 V51-V53 V55 V57 V58 = SENSE_PAD: Item Num: P23-SENSE; Manufacturer: NONE; Manufacturer Part Num: NONE
C421 C443 C454 C455 C458 C459 C477 C480 C866-C871 = CAP: CAP -   CER, 100UF, 10V, 20%, X5R, 1206, HIEGHT 1.6mm; AGILE_LINK: http://sj-agile9app/Agile/PLMServlet?action=OpenEmailObject&classid=10000&objid=146494148; CAPACITANCE: 47uF; Item Num: P03-17591R; LIFECYCLE_PHASE: Active; MFR_LIFECYCLE: Active; Manufacturer: TDK Electronics; Manufacturer Part Num: C3216X51A107M; Num Pins: 2; PART_SUBCLASS: CAPACITORS; RATED_VOLTAGE: 10V; RoHS Compliant: RoHS Compliant; TOLERANCE: 20%
C482 C483 = CAP: CAP - CER, 22PF, 50V, +/-5%, NP0, 0402 SMD; AGILE_LINK: http://sj-agile9app/Agile/PLMServlet?action=OpenEmailObject&classid=10000&objid=213459014; Item Num: P03-16312R; Lead Free Status: Lead Free; MFR_LIFECYCLE: Active; Manufacturer: Phycomp / Yageo; Manufacturer Part Num: CC0402JRNPO9BN220; Num Pins: 2; PART_SUBCLASS: CAPACITORS; RoHS Compliant: Yes
C484 C485 = CAP: CAP - CER, 47000PF, 25V, X7R, 0402; Item Num: P03-15073R; Lead Free Status: Yes; Manufacturer: Murata; Manufacturer Part Num: GRM155R71E473KA88D; Num Pins: 2; Part Class: Capacitors; Price: 0; RoHS Compliant: Yes; Supplier Part Num: GRM155R71E473KA88D
C486 C487 = CAP: CAP - CERAMIC, 0.22UF, 10V, X5R, 10%, 0402; AGILE_LINK: http://sj-agile9app/Agile/PLMServlet?action=OpenEmailObject&classid=10000&objid=250793653; Item Num: P03-15149R; LIFECYCLE_PHASE: Active; MFR_LIFECYCLE: Active; Manufacturer: Murata; Manufacturer Part Num: GRM155R61A224KE19D; Num Pins: 2; PART_SUBCLASS: CAPACITORS; RATED_VOLTAGE: 10V; RoHS Compliant: RoHS Compliant; TOLERANCE: +/-10%
R473 R480 R488 R489 R493 R498 = RESISTOR: RES - 294K OHM, 1/16W, 1%, 0402 SMD; Item Num: P02-16127R; Manufacturer: Vishay; Manufacturer Part Num: CRCW0402294KFKED
R474 R483 = RESISTOR: RES ZERO OHM 1/16W 5% 0402 SMD; Item Num: P02-14020R; Lead Free Status: No; Manufacturer: Panasonic; Manufacturer Part Num: ERJ-2GE0R00X; Num Pins: 2; Part Class: RESISTORS; RoHS Compliant: Yes; Tolerance: 5%
R475 R484 = RESISTOR: RES, 10 OHM, 1%, 1/16W, 0402; AGILE_LINK: http://sj-agile9app/Agile/PLMServlet?action=OpenEmailObject&classid=10000&objid=146932246; Item Num: P02-16268R; LIFECYCLE_PHASE: Active; MFR_LIFECYCLE: Active; Manufacturer: Panasonic; Manufacturer Part Num: ERJ-2RKF10R0X; Num Pins: 2; PART_SUBCLASS: RESISTORS; POWER: 1/16W; RoHS Compliant: RoHS Compliant; TOLERANCE: +/-1%
R476-R478 R485 = RESISTOR: RES ZERO OHM 1/16W 5% 0402 SMD; Altera Part No.: P02-14020R; Item Num: P02-14020R; Lead Free Status: No; Manufacturer: Panasonic; Manufacturer Part Num: ERJ-2GE0R00X; Num Pins: 2; Part Class: RESISTORS; Price: 0; RoHS Compliant: Yes; Tolerance: 5%
R479 R481 = RESISTOR: RES, 15K OHM, 1%, 1/16W, 0402, SMD; Item Num: P02-11397R; Lead Free Status: Yes; Manufacturer: Panasonic; Manufacturer Part Num: ERJ-2RKF1502X; Num Pins: 2; Part Class: RESISTORS; Price: 0; RoHS Compliant: Yes
R482 = RESISTOR: RES - SMD 1/16WATT 976KOHMS 1% 0402; Item Num: P02-17638R; Lead Free Status: No; Manufacturer: Vishay; Manufacturer Part Num: CRCW0402976KFKED; Num Pins: 2; Part Class: RESISTORS; Price: 0; RoHS Compliant: Yes; Tolerance: 1%
R490 R495 = RES: RES SMD 3.48M OHM 1% 1/16W 0402; Item Num: P02-17840R; Manufacturer: Vishay Dale; Manufacturer Part Num: CRCW04023M48FKED; Package: SMD; Part Class: RESISTORS; Type: Resistor
R491 R496 = RES: RES SMD 1.15M OHM 1% 1/16W 0402; Item Num: P02-17841R; Manufacturer: Vishay Dale; Manufacturer Part Num: CRCW04021M15FKED; Package: SMD; Part Class: RESISTORS; Type: Resistor
R492 R497 = RES: RES 576K OHM 1/10W 1% 0402 SM; Item Num: P02-17110R; Manufacturer: Panasonic; Manufacturer Part Num: ERJ-2RKF5763X; Package: SMD; Part Class: RESISTORS; Type: Resistor
R494 R5286 = RES: RES SMD 1.69M OHM 1% 1/16W 0402; Item Num: P02-17844R; Manufacturer: Vishay Dale; Manufacturer Part Num: CRCW04021M69FKED; Package: SMD; Part Class: RESISTORS; Type: Resistor
R499 R500 = RESISTOR: RES - 5.49K OHM, 1/16W, 1%, 0402 SMD; AGILE_LINK: http://sj-agile9app/Agile/PLMServlet?action=OpenEmailObject&classid=10000&objid=146548997; Item Num: P02-16004R; LIFECYCLE_PHASE: Active; Lead Free Status: Yes; MFR_LIFECYCLE: Active; Manufacturer: Panasonic; Manufacturer Part Num: ERJ-2RKF5491X; Num Pins: 2; PART_SUBCLASS: RESISTORS; POWER: 1/16W; RoHS Compliant: Yes; TOLERANCE: +/-1%
U72 U73 = EN6362QI: Regulator, 8A Sync DC-DC Buck with integrated Inductor; Item Num: P05-18774R; Manufacturer: Enpirion
C409 C410 C430 C431 C450 C451 = PCAP: CAP TANT POLY 100UF 16V 2917; Item Num: P03-17867R; LIFECYCLE_PHASE: Active; Lead Free Status: Lead Free; MFR_LIFECYCLE: Active; Manufacturer: Panasonic; Manufacturer Part Num: 16TQC100MYF; Num Pins: 2; PART_SUBCLASS: CAPACITORS; RoHS Compliant: RoHS Compliant; TOLERANCE: +/-20%; Working Voltage: 16V
C416-C419 C436-C439 C799-C802 = CAP: CAP - CER 100UF 6.3V X5R 1206; Dielectric: X5R; Item Num: P03-15292R; Manufacturer: Murata; Manufacturer Part Num: GRM31CR60J107ME39L; RATED_VOLTAGE: 6.3v; RoHS Compliant: Yes; Tolerance: 20%; Working Voltage: 6.3V
C423 C425 C442 C444 = CAP: CAP CER 10UF 25V 20% JB 0603; Item Num: P03-17784R; Lead Free Status: Yes; Manufacturer: TDK; Manufacturer Part Num: C1608JB1E106M080AC; Num Pins: 2; Part Class: Capacitors; Price: 0; RoHS Compliant: Yes
C426 C445 C457 C461 = CAP: CAP - CER 1NF 50V C0G 0402; Item Num: P03-15273R; Lead Free Status: Yes; Manufacturer: Murata; Manufacturer Part Num: GRM1555C1H102JA01D; Num Pins: 2; Part Class: Capacitors; Price: 0; RoHS Compliant: Yes
C446 C817 = CAP: CAP - CERAMIC, 4.7UF, 6.3V, 10%, X5R, 0402; AGILE_LINK: http://sj-agile9app/Agile/PLMServlet?action=OpenEmailObject&classid=10000&objid=257560276; Item Num: P03-17432R; LIFECYCLE_PHASE: Active; Lead Free Status: Not Lead Free; MFR_LIFECYCLE: Active; Manufacturer: Murata; Manufacturer Part Num: GRM155R60J475ME87D; Num Pins: 2; PART_SUBCLASS: CAPACITORS; RATED_VOLTAGE: 6.3V; RoHS Compliant: RoHS Compliant; TOLERANCE: +/-10%
R421 R426 R431 R435 = RESISTOR: RES,10.0K OHMS,1.0%,1/16W, 0402; AGILE_LINK: http://sj-agile9app/Agile/PLMServlet?action=OpenEmailObject&classid=10000&objid=146548997; Item Num: P02-11364R; LIFECYCLE_PHASE: Active; Lead Free Status: No; MFR_LIFECYCLE: Active; Manufacturer: Panasonic; Manufacturer Part Num: ERJ-2RKF1002X; Num Pins: 2; PART_SUBCLASS: RESISTORS; POWER: 1/16W; RESISTANCE: 10K; RoHS Compliant: Yes; TOLERANCE: +/-1%
R422 R427 R432 R436 = RESISTOR: 0.00025 1% 4WATT SENSE RESISTOR 2725 CASE; AGILE_LINK: http://sj-agile9app/Agile/PLMServlet?action=OpenEmailObject&classid=10000&objid=260822062; Item Num: P02-17631R; LIFECYCLE_PHASE: Active; MFR_LIFECYCLE: Active; Manufacturer: Stackpole Electronics, Inc; Manufacturer Part Num: CSS2725FTL250; Num Pins: 2; PART_SUBCLASS: RESISTORS; RoHS Compliant: RoHS Compliant
R428 = RESISTOR_0402: RES - 30.1K OHM, 1/16W, 1%, 0402, SMD; Manufacturer: Vishay; Manufacturer Part Num: CRCW040230K1FKED; Manufacturer Part Number: CRCW040230K1FKED; item Num: P02-14276R
R429 = RESISTOR: RES,100K OHMS,1.0%,1/16W,0402; Item Num: P02-11386R; Lead Free Status: No; Manufacturer: Panasonic; Manufacturer Part Num: ERJ-2RKF1003X; Num Pins: 2; Part Class: Resistors; Price: 0; RoHS Compliant: Yes
R430 = RESISTOR: RES - 133K OHM, 1/10W, 1%, 0402 SMD; Item Num: P02-17574R; Lead Free Status: No; Manufacturer: Panasonic; Manufacturer Part Num: ERJ-2RKF1333X; Num Pins: 2; Part Class: RESISTORS; Price: 0; RoHS Compliant: Yes; Tolerance: 1%
U68 = LTM4630A: IC, Dual 18A or Single 36A DC/DC Umodule Regulator; Item Num: P05-18772R; Manufacturer: Linear Technology; Manufacturer Part Num: LTM4630AEV#PBF
C456 C460 = PCAP: CAP TANT 470UF 6.3V 20% SMD, T530 POLYMER TANTALUM KO-CAP, LOW ESR 5 MOHM; Item Num: P03-17578R; LIFECYCLE_PHASE: Active; Lead Free Status: Lead Free; MFR_LIFECYCLE: Active; Manufacturer: Kemet; Manufacturer Part Num: T530Y477M006ATE005; Num Pins: 2; PART_SUBCLASS: CAPACITORS; RoHS Compliant: RoHS Compliant; TOLERANCE: +/-20%; Working Voltage: 6.3V
R433 R438 = RESISTOR: RES SMD 215K OHM 1% 1/10W 0402; Item Num: P02-17873R; Lead Free Status: No; Manufacturer: Panasonic; Manufacturer Part Num: ERJ-S02F2153X; Num Pins: 2; Part Class: RESISTORS; Price: 0; RoHS Compliant: Yes; Tolerance: 1%
R434 R439 = RESISTOR: RES - 69.8K OHM, 1/10W, 1%, 0402, SMD; AGILE_LINK: http://sj-agile9app/Agile/PLMServlet?action=OpenEmailObject&classid=10000&objid=146548997; Item Num: P02-17462R; LIFECYCLE_PHASE: Active; Lead Free Status: No; MFR_LIFECYCLE: Active; Manufacturer: Panasonic; Manufacturer Part Num: ERJ-2RKF6982x; Num Pins: 2; PART_SUBCLASS: RESISTORS; POWER: 1/10W; RoHS Compliant: Yes; TOLERANCE: +/-1%
R437 = RESISTOR: RES 169K OHM 1/16W 1% 0402 SMD; AGILE_LINK: http://sj-agile9app/Agile/PLMServlet?action=OpenEmailObject&classid=10000&objid=146548997; Item Num: P02-17210R; LIFECYCLE_PHASE: Active; Lead Free Status: No; MFR_LIFECYCLE: Active; Manufacturer: Vishay; Manufacturer Part Num: CRCW0402169KFKED; Num Pins: 2; PART_SUBCLASS: RESISTORS; POWER: 1/16W; RoHS Compliant: Yes; TOLERANCE: +/-1%
U69 = LTM4650EY: REG DUAL 25A OR SINGLE 50A DC/DC ?MODULE REGULATOR; Item Num: P05-18766R; Manufacturer: Linear Technology; Manufacturer Part Num: LTM4650EY#PBF; Manufacturer Part Number: LTM4650EY#PBF
C424 = CAP_47UF_+_-20%_6.3V_1206: CAP CER 47UF 6.3V 20% X5R 0805; Item Num: P03-17612R; Manufacturer: Taiyo Yuden; Manufacturer Part Num: JMK212BJ476MG-T
C427 = CAP: CAP, CERAMIC, 330PF, 0603, 5%, 50VDC, NPO; Item Num: P03-11679R; Lead Free Status: Yes; Manufacturer: Murata; Manufacturer Part Num: GRM1885C1H331JA01D; Num Pins: 2; Part Class: Capacitors; Price: 0; RoHS Compliant: Yes
C428 = CAP: CAP CER 150PF 50V NP0 0402 +/-5%; Item Num: P03-17893R; Lead Free Status: Yes; Manufacturer: Murata; Manufacturer Part Num: GRM1555C1H151JA01D; Num Pins: 2; Part Class: Capacitors; Price: 0; RoHS Compliant: Yes
L28 = BEAD_FERRITE_SM: FERRITE BEAD 120 OHM 0402, 1A,; Item Num: P01-17086R; LIFECYCLE_PHASE: Active; MFR_LIFECYCLE: Active; Manufacturer: Taiyo Yuden; Manufacturer Part Num: BKP1005HS121-T; Num Pins: 2; PART_SUBCLASS: INDUCTORS; Part Class: Inductors; RoHS Compliant: Yes
R423 = RESISTOR: RES - 97.6K OHM, 1/10W, 1%, 0402 SMD; Item Num: P02-17552R; Lead Free Status: No; Manufacturer: Panasonic; Manufacturer Part Num: ERJ-2RKF9762X; Num Pins: 2; Part Class: Resistors; Price: 0; RoHS Compliant: Yes
R424 = RESISTOR: RES - 255K OHM, 1/16W, +/-1%, 0402 SMD; Item Num: P02-16272R; Lead Free Status: No; Manufacturer: Panasonic; Manufacturer Part Num: ERJ-2RKF2553X; Num Pins: 2; Part Class: RESISTORS; Price: 0; RoHS Compliant: Yes; Tolerance: 1%
R425 = RESISTOR_0402: RES,118K OHMS,1.0%,1/10W,0402; Manufacturer: Panasonic; Manufacturer Part Num: ERJ-2RKF1183X; Manufacturer Part Number: ERJ-2RKF1183X; item Num: P02-17487R
U67 = LTM4627EY: REG - 15A DC/DC uMODULE, Vin 4.5V-20V, Vout 0.6V-5V, BGA; Item Num: P05-18785R; Manufacturer: Linear Technology; Manufacturer Part Num: LTM4627EY#PBF; Manufacturer Part Number: LTM4627EY#PBF

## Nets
1.8V: C443.1 R427.2 V41.2(SNS) V43.1(RSNS) ; also on sheet 6 9 15 16 17 19 20 24 27 28 29 30 31 45
1.8V_DAC: R430.1 ; also on sheet 31
1.8V_ISENSE_N: V41.1(RSNS) ; also on sheet 32
1.8V_ISENSE_P: V40.1(RSNS) ; also on sheet 32
1.8V_LOW: C436.1 C437.1 C438.1 C439.1 C440.2 C441.2 C442.1 C444.1 C799.1 C800.1 C801.1 C802.1 R427.1 U68.A1(VOUT1_1) U68.A2(VOUT1_2) U68.A3(VOUT1_3) U68.A4(VOUT1_4) U68.A5(VOUT1_5) U68.A8(VOUT2_1) U68.A9(VOUT2_2) U68.A10(VOUT2_3) U68.A11(VOUT2_4) U68.A12(VOUT2_5) U68.B1(VOUT1_6) U68.B2(VOUT1_7) U68.B3(VOUT1_8) U68.B4(VOUT1_9) U68.B5(VOUT1_10) U68.B8(VOUT2_6) U68.B9(VOUT2_7) U68.B10(VOUT2_8) U68.B11(VOUT2_9) U68.B12(VOUT2_10) U68.C1(VOUT1_11) U68.C2(VOUT1_12) U68.C3(VOUT1_13) U68.C4(VOUT1_14) U68.C9(VOUT2_11) U68.C10(VOUT2_12) U68.C11(VOUT2_13) U68.C12(VOUT2_14) V40.2(SNS) ; also on sheet 18 46
1.8V_PWRGD: R426.1 U68.G8(PGOOD2) U68.G9(PGOOD1)
1.8V_SENSE_N: U68.E9(DIFFN) V44.2(SNS)
1.8V_SENSE_P: U68.E8(DIFFP) V43.2(SNS)
3.3V_REG: C462.2 C472.2 C473.2 C478.2 C481.2 R440.2 R443.1 R458.1 R475.2 R477.2 R478.2 R484.2 R486.2 R487.2 U70.19(PVIN) U70.20(PVIN) U70.21(PVIN) U70.33(AVIN) U72.29(PVIN1) U72.30(PVIN2) U72.31(PVIN3) U72.32(PVIN4) U72.33(PVIN5) U72.34(PVIN6) U72.35(PVIN7) U72.36(PVIN8) U72.59(PVIN9) U73.29(PVIN1) U73.30(PVIN2) U73.31(PVIN3) U73.32(PVIN4) U73.33(PVIN5) U73.34(PVIN6) U73.35(PVIN7) U73.36(PVIN8) U73.59(PVIN9) ; also on sheet 31 34 43 44
12V_G1: C409.1 C410.1 C411.2 C412.2 C413.2 C414.2 C415.2 U67.A1(VIN1) U67.A2(VIN2) U67.A3(VIN3) U67.A4(VIN4) U67.A5(VIN5) U67.A6(VIN6) U67.B1(VIN7) U67.B2(VIN8) U67.B3(VIN9) U67.B4(VIN10) U67.B5(VIN11) U67.B6(VIN12) U67.C1(VIN13) U67.C2(VIN14) U67.C3(VIN15) U67.C4(VIN16) U67.C5(VIN17) U67.C6(VIN18) ; also on sheet 31 33 35 36 37
12V_G2: C429.2 C430.1 C431.1 C432.2 C433.2 C434.2 C435.2 C447.2 C448.2 C449.2 C450.1 C451.1 C452.2 C453.2 U68.J2(VIN21) U68.J3(VIN22) U68.J4(VIN23) U68.J9(VIN24) U68.J10(VIN25) U68.J11(VIN26) U68.K2(VIN27) U68.K3(VIN28) U68.K4(VIN29) U68.K9(VIN30) U68.K10(VIN31) U68.K11(VIN32) U68.L2(VIN11) U68.L3(VIN12) U68.L4(VIN13) U68.L5(VIN14) U68.L6(VIN15) U68.L7(VIN16) U68.L8(VIN17) U68.L9(VIN18) U68.L10(VIN19) U68.L11(VIN20) U68.M2(VIN1) U68.M3(VIN2) U68.M4(VIN3) U68.M5(VIN4) U68.M6(VIN5) U68.M7(VIN6) U68.M8(VIN7) U68.M9(VIN8) U68.M10(VIN9) U68.M11(VIN10) U69.J2(VIN21) U69.J3(VIN22) U69.J4(VIN23) U69.J9(VIN24) U69.J10(VIN25) U69.J11(VIN26) U69.K2(VIN27) U69.K3(VIN28) U69.K4(VIN29) U69.K9(VIN30) U69.K10(VIN31) U69.K11(VIN32) U69.L2(VIN11) U69.L3(VIN12) U69.L4(VIN13) U69.L5(VIN14) U69.L6(VIN15) U69.L7(VIN16) U69.L8(VIN17) U69.L9(VIN18) U69.L10(VIN19) U69.L11(VIN20) U69.M2(VIN1) U69.M3(VIN2) U69.M4(VIN3) U69.M5(VIN4) U69.M6(VIN5) U69.M7(VIN6) U69.M8(VIN7) U69.M9(VIN8) U69.M10(VIN9) U69.M11(VIN10) ; also on sheet 31 33 43
GND: C409.2 C410.2 C411.1 C412.1 C413.1 C414.1 C415.1 C416.2 C417.2 C418.2 C419.2 C420.1 C421.2 C422.1 C423.2 C424.2 C425.2 C426.1 C428.1 C429.1 C430.2 C431.2 C432.1 C433.1 C434.1 C435.1 C436.2 C437.2 C438.2 C439.2 C440.1 C441.1 C442.2 C443.2 C444.2 C445.2 C446.1 C447.1 C448.1 C449.1 C450.2 C451.2 C452.1 C453.1 C454.2 C455.2 C456.2 C457.1 C458.2 C459.2 C460.2 C461.1 C462.1 C463.2 C464.2 C470.1 C472.1 C473.1 C474.2 C475.2 C476.2 C477.2 C478.1 C479.2 C480.2 C481.1 C484.2 C485.2 C799.2 C800.2 C801.2 C802.2 C817.1 C866.2 C867.2 C868.2 C869.2 C870.2 C871.2 R423.1 R425.1 R428.1 R429.1 R434.2 R437.1 R439.2 R450.1 R451.1 R454.1 R461.1 R465.1 R469.1 R476.1 R485.1 R488.1 R489.1 R499.2 R500.2 U67.A8(MODE_PLLIN) U67.B7(GND1) U67.B9(GND2) U67.C7(GND3) U67.C9(GND4) U67.D1(GND5) U67.D2(GND6) U67.D3(GND7) U67.D4(GND8) U67.D5(GND9) U67.D6(GND10) U67.D8(GND11) U67.E1(GND12) U67.E2(GND13) U67.E3(GND14) U67.E4(GND15) U67.E5(GND16) U67.E6(GND17) U67.E7(GND18) U67.E9(GND19) U67.F1(GND20) U67.F2(GND21) U67.F3(GND22) U67.F4(GND23) U67.F5(GND24) U67.F6(GND25) U67.F7(GND26) U67.F8(GND27) U67.F9(GND28) U67.G1(GND29) U67.G2(GND30) U67.G3(GND31) U67.G4(GND32) U67.G5(GND33) U67.G6(GND34) U67.G7(GND35) U67.G8(GND36) U67.G9(GND37) U67.G11(SGND1) U67.H1(GND40) U67.H2(GND41) U67.H3(GND42) U67.H4(GND43) U67.H5(GND44) U67.H6(GND45) U67.H7(GND46) U67.H8(GND39) U67.H9(GND38) U67.H11(SGND2) U67.H12(SGND3) U68.A6(GND1) U68.A7(GND2) U68.B6(GND3) U68.B7(GND4) U68.C7(SGND4) U68.D1(GND5) U68.D2(GND6) U68.D3(GND7) U68.D4(GND8) U68.D6(SGND5) U68.D9(GND9) U68.D10(GND10) U68.D11(GND11) U68.D12(GND12) U68.E1(GND13) U68.E2(GND14) U68.E3(GND15) U68.E4(GND16) U68.E10(GND17) U68.E11(GND18) U68.E12(GND19) U68.F1(GND20) U68.F2(GND21) U68.F3(GND54) U68.F4(MODE_PLLIN) U68.F6(SGND2) U68.F7(SGND3) U68.F10(GND53) U68.F11(GND52) U68.F12(GND51) U68.G1(GND50) U68.G3(GND49) U68.G4(PHASMD) U68.G6(SGND6) U68.G7(SGND1) U68.G10(GND48) U68.G12(GND47) U68.H1(GND46) U68.H2(GND45) U68.H3(GND44) U68.H4(GND43) U68.H5(GND42) U68.H6(GND41) U68.H7(GND40) U68.H9(GND39) U68.H10(GND38) U68.H11(GND37) U68.H12(GND36) U68.J1(GND35) U68.J5(GND34) U68.J8(GND33) U68.J12(GND32) U68.K1(GND31) U68.K5(GND30) U68.K6(GND29) U68.K7(GND28) U68.K8(GND27) U68.K12(GND26) U68.L1(GND25) U68.L12(GND24) U68.M1(GND23) U68.M12(GND22) U69.A6(GND1) U69.A7(GND2) U69.B6(GND3) U69.B7(GND4) U69.C7(SGND1) U69.D1(GND5) U69.D2(GND6) U69.D3(GND7) U69.D4(GND8) U69.D6(SGND2) U69.D9(GND9) U69.D10(GND10) U69.D11(GND11) U69.D12(GND12) U69.E1(GND13) U69.E2(GND14) U69.E3(GND15) U69.E4(GND16) U69.E10(GND17) U69.E11(GND18) U69.E12(GND19) U69.F1(GND20) U69.F2(GND21) U69.F3(GND22) U69.F4(MODE_PLLIN) U69.F6(SGND5) U69.F7(SGND6) U69.F10(GND23) U69.F11(GND24) U69.F12(GND25) U69.G1(GND26) U69.G3(GND27) U69.G4(PHASMD) U69.G6(SGND3) U69.G7(SGND4) U69.G10(GND28) U69.G12(GND29) U69.H1(GND30) U69.H2(GND31) U69.H3(GND32) U69.H4(GND33) U69.H5(GND34) U69.H6(GND35) U69.H7(GND36) U69.H9(GND37) U69.H10(GND38) U69.H11(GND39) U69.H12(GND40) U69.J1(GND41) U69.J5(GND42) U69.J8(GND43) U69.J12(GND44) U69.K1(GND45) U69.K5(GND54) U69.K6(GND53) U69.K7(GND52) U69.K8(GND51) U69.K12(GND50) U69.L1(GND49) U69.L12(GND48) U69.M1(GND47) U69.M12(GND46) U70.13(PGND) U70.14(PGND) U70.15(PGND) U70.16(PGND) U70.17(PGND) U70.18(PGND) U70.32(AGND) U70.39(PGND) U72.24(PGND1) U72.25(PGND2) U72.26(PGND3) U72.27(PGND4) U72.28(PGND5) U72.44(AGND) U72.57(PGND(THRM)) U73.24(PGND1) U73.25(PGND2) U73.26(PGND3) U73.27(PGND4) U73.28(PGND5) U73.44(AGND) U73.57(PGND(THRM)) V39.1(RSNS) V44.1(RSNS) V52.2(SNS) ; also on sheet 6 7 8 9 10 11 12 13 14 15 16 17 18 19 20 21 23 24 25 27 28 29 30 31 32 33 34 35 36 37 43 44 45 46
VCCIO_FMCA_ISENSE_N: V55.1(RSNS) ; also on sheet 32
VCCIO_FMCA_ISENSE_P: V53.1(RSNS) ; also on sheet 32
VCCIO_FMCA_PWRGD: R440.1 U70.28(POK)
VCCIO_HILO_ISENSE_N: V58.1(RSNS) ; also on sheet 32
VCCIO_HILO_ISENSE_P: V57.1(RSNS) ; also on sheet 32
VCCR_ISENSE_N: V49.1(RSNS) ; also on sheet 32
VCCR_ISENSE_P: V48.1(RSNS) ; also on sheet 32
VCCR_PWRGD: R435.1 U69.G8(PGOOD2)
VCCRAM_ISENSE_N: V36.1(RSNS) ; also on sheet 32
VCCRAM_ISENSE_P: V35.1(RSNS) ; also on sheet 32
VCCRAM_PWRGD: R421.1 U67.F11(PGOOD1) U67.G12(PGOOD2)
VCCT_ISENSE_N: V46.1(RSNS) ; also on sheet 32
VCCT_ISENSE_P: V45.1(RSNS) ; also on sheet 32
VCCT_PWRGD: R431.1 U69.G9(PGOOD1)
VDD_1.3V_SET: R494.1 ; also on sheet 23
VDD_1.5V_SET: R492.1 ; also on sheet 23
VDD_1.8V_SET: R493.1 ; also on sheet 23
VDD_1.25V_SET: R490.1 ; also on sheet 23
VDD_1.35V_SET: R491.1 ; also on sheet 23
VDDQ_1.3V_SET: R5286.1 ; also on sheet 23
VDDQ_1.5V_SET: R497.1 ; also on sheet 23
VDDQ_1.8V_SET: R498.1 ; also on sheet 23
VDDQ_1.25V_SET: R495.1 ; also on sheet 23
VDDQ_1.35V_SET: R496.1 ; also on sheet 23
EN_1.8V: U68.F5(RUN1) U68.F9(RUN2) ; also on sheet 31 46
EN_S10_VCCIO_FMCA: R446.1 ; also on sheet 31 33 46
EN_S10_VCCIO_HILO: R474.2 R483.2 ; also on sheet 31 46
EN_S10_VCCR: U69.F9(RUN2) ; also on sheet 31 46
EN_S10_VCCRAM: U67.A10(RUN) ; also on sheet 31 46
EN_S10_VCCT: U69.F5(RUN1) ; also on sheet 31 46
FMCA_ADJ: C463.1 C464.1 R445.1 U70.5(VOUT) U70.6(VOUT) U70.7(VOUT) U70.8(VOUT) U70.9(VOUT) U70.10(VOUT) U70.11(VOUT) V53.2(SNS) ; also on sheet 46
FMCA_ADJ_VFB: C468.1 R448.1 R451.2 R456.2 R460.2 R464.2 R468.2 U70.31(VFB)
HILO_VDD: C475.1 C476.1 C477.1 C482.1 R473.2 U72.15(VOUT1) U72.16(VOUT2) U72.17(VOUT3) U72.18(VOUT4) U72.47(VSENSE) U72.58(VOUT5) ; also on sheet 23 46
HILO_VDD_PWRGD: R486.1 U72.48(PGOOD)
HILO_VDDQ: C474.1 C479.1 R472.1 U73.15(VOUT1) U73.16(VOUT2) U73.17(VOUT3) U73.18(VOUT4) U73.58(VOUT5) V57.2(SNS) ; also on sheet 23 46
HILO_VDDQ_PWRGD: R487.1 U73.48(PGOOD)
S10_FMCA_ENABLE: R443.2 R446.2 U70.27(ENA)
S10_VCCIO_FMCA: C468.2 R445.2 R448.2 V55.2(SNS) ; also on sheet 9 15 25 31 45
S10_VCCIO_FMCA_DAC: R456.1 ; also on sheet 31
S10_VCCIO_HILO: C480.1 C483.1 R472.2 R480.2 U73.47(VSENSE) V58.2(SNS) ; also on sheet 15 31 45
S10_VCCIO_HILO_DAC: R482.1 ; also on sheet 31
S10_VCCPLLDIG_SDM: C424.1 L28.1 ; also on sheet 15
S10_VCCR_DAC: R438.1 ; also on sheet 31
S10_VCCR_GXB: R436.2 V49.2(SNS) V51.2(SNS) ; also on sheet 15 31 45
S10_VCCR_GXB_LOW: C458.1 C459.1 C460.1 C869.1 C870.1 C871.1 R436.1 U69.A8(VOUT2_1) U69.A9(VOUT2_2) U69.A10(VOUT2_3) U69.A11(VOUT2_4) U69.A12(VOUT2_5) U69.B8(VOUT2_6) U69.B9(VOUT2_7) U69.B10(VOUT2_8) U69.B11(VOUT2_9) U69.B12(VOUT2_10) U69.C9(VOUT2_11) U69.C10(VOUT2_12) U69.C11(VOUT2_13) U69.C12(VOUT2_14) V48.2(SNS) ; also on sheet 46
S10_VCCR_SENSE_N: U69.E9(DIFFN) V52.1(RSNS)
S10_VCCR_SENSE_P: U69.E8(DIFFP) V51.1(RSNS)
S10_VCCRAM: C421.1 L28.2 R422.2 V36.2(SNS) V38.1(RSNS) ; also on sheet 15 31 45
S10_VCCRAM_DAC: R424.1 ; also on sheet 31
S10_VCCRAM_LOW: C416.1 C417.1 C418.1 C419.1 C420.2 C422.2 C423.1 C425.1 C427.2 R422.1 U67.J1(VOUT1) U67.J2(VOUT2) U67.J3(VOUT3) U67.J4(VOUT4) U67.J5(VOUT5) U67.J6(VOUT6) U67.J7(VOUT7) U67.J8(VOUT8) U67.J9(VOUT9) U67.J10(VOUT10) U67.K1(VOUT11) U67.K2(VOUT12) U67.K3(VOUT13) U67.K4(VOUT14) U67.K5(VOUT15) U67.K6(VOUT16) U67.K7(VOUT17) U67.K8(VOUT18) U67.K9(VOUT19) U67.K10(VOUT20) U67.K11(VOUT21) U67.L1(VOUT22) U67.L2(VOUT23) U67.L3(VOUT24) U67.L4(VOUT25) U67.L5(VOUT26) U67.L6(VOUT27) U67.L7(VOUT28) U67.L8(VOUT29) U67.L9(VOUT30) U67.L10(VOUT31) U67.L11(VOUT32) U67.M1(VOUT33) U67.M2(VOUT34) U67.M3(VOUT35) U67.M4(VOUT36) U67.M5(VOUT37) U67.M6(VOUT38) U67.M7(VOUT39) U67.M8(VOUT40) U67.M9(VOUT41) U67.M10(VOUT42) U67.M11(VOUT43) V35.2(SNS) ; also on sheet 46
S10_VCCRAM_SENSE_N: U67.M12(VOSNS-) V39.2(SNS)
S10_VCCRAM_SENSE_P: U67.J12(VOSNS+) V38.2(SNS)
S10_VCCT_DAC: R433.1 ; also on sheet 31
S10_VCCT_GXB: R432.2 V46.2(SNS) ; also on sheet 15 31 45
S10_VCCT_GXB_LOW: C454.1 C455.1 C456.1 C866.1 C867.1 C868.1 R432.1 U69.A1(VOUT1_1) U69.A2(VOUT1_2) U69.A3(VOUT1_3) U69.A4(VOUT1_4) U69.A5(VOUT1_5) U69.B1(VOUT1_6) U69.B2(VOUT1_7) U69.B3(VOUT1_8) U69.B4(VOUT1_9) U69.B5(VOUT1_10) U69.C1(VOUT1_11) U69.C2(VOUT1_12) U69.C3(VOUT1_13) U69.C4(VOUT1_14) U69.C5(VOUTS1) V45.2(SNS) ; also on sheet 46
N17322031: R450.2 U70.26(SYNC/LLM)
N17322109: R454.2 U70.29(RLLM)
N17322122: C470.2 U70.30(SS)
N17322175: R458.2 U70.22(NC22)
N17322493: R468.1 R469.2
N17322495: R460.1 R461.2
N17322497: R464.1 R465.2
N17328577: R477.1 R483.1 R485.2 U72.41(ENABLE)
N17328579: R484.1 U72.43(AVIN)
N17328583: C487.1 U72.39(VDDB)
N17328587: C487.2 U72.40(BGND)
N17328617: R473.1 R479.1 R488.2 R490.2 R491.2 R492.2 R493.2 R494.2 U72.42(VFB)
N17328687: C485.1 U72.46(SS)
N17328919: C482.2 R479.2
N17330097: R474.1 R476.2 R478.1 U73.41(ENABLE)
N17330103: C486.1 U73.39(VDDB)
N17330107: C486.2 U73.40(BGND)
N17330135: R480.1 R481.1 R482.2 R489.2 R495.2 R496.2 R497.2 R498.2 R5286.2 U73.42(VFB)
N17330205: C484.1 U73.46(SS)
N17330449: C483.2 R481.2
N17349947: R433.2 R434.1 U69.D5(VFB1)
N17349969: R438.2 R439.1 U69.D7(VFB2)
N17350742: C461.2 U69.D8(TRACK2)
N17350792: C457.2 U69.E5(TRACK1)
N17351773: U69.C8(VOUTS2) U69.F8(DIFFOUT)
N17352342: R437.2 U69.C6(FSET)
N17353010: C817.2 R431.2 R435.2 U69.H8(INTVCC)
N17364018: C446.2 R426.2 U68.H8(INTVCC)
N17419014: R428.2 R430.2 U68.D5(VFB1) U68.D7(VFB2)
N17460962: R421.2 U67.A7(INTVCC1) U67.D9(INTVCC2)
N17461123: R423.2 U67.B12(FSET)
N17461127: C426.2 U67.A9(TRACK/SS)
N17461358: U67.K12(DIFF_OUT) U67.L12(VOUT_LCL)
N17461364: C427.1 R424.2 R425.2 U67.F12(VFB)
N17467098: C428.2 U67.A11(COMP)
N18656380: R475.1 U73.43(AVIN)
N18895056: U68.C5(VOUTS1) U68.F8(DIFFOUT)
N18895714: R429.2 U68.C6(FSET)
N18897588: U68.E6(COMP1) U68.E7(COMP2)
N18897706: C445.1 U68.D8(TRACK2) U68.E5(TRACK1)
N22372157: R500.1 U73.45(FQADJ)
N22372158: R499.1 U72.45(FQADJ)

Not connected (* = marked no-connect by the designer): U67 A12(MTP1)* B11(MTP2)* C10(MTP3)* C11(MTP4)* C12(MTP5)* D10(MTP6)* D11(MTP7)* D12(MTP8)* E12(EXTVCC)*; U68 C8(VOUTS2)* G2(SW1)* G5(CLKOUT)* G11(SW2)* J6(TEMP)* J7(EXTVCC)*; U69 E6(COMP1)* E7(COMP2)* G2(SW1)* G5(CLKOUT)* G11(SW2)* J6(TEMP)* J7(EXTVCC)*; U70 1(NC(SW)1)* 2(NC(SW)2)* 3(NC3)* 4(NC4)* 12(NC(SW)12)* 23(NC23)* 24(NC24)* 25(NC25)* 34(NC(SW)34)* 35(NC(SW)35)* 36(NC(SW)36)* 37(NC(SW)37)* 38(NC(SW)38)*; U72 1(NC1)* 2(NC2)* 3(NC3)* 4(NC4)* 5(NC5)* 6(NC6)* 7(NC7)* 8(NC8)* 9(NC9)* 10(NC10)* 11(NC11)* 12(NC12)* 13(NC13)* 14(NC14)* 19(NC15)* 20(NC16)* 21(NC17)* 22(NC18)* 23(NC(SW)1)* 37(NC19)* 38(NC20)* 49(NC(SW)2)* 50(NC(SW)3)* 51(NC(SW)4)* 52(NC(SW)5)* 53(NC21)* 54(NC22)* 55(NC23)* 56(NC24)*; U73 1(NC1)* 2(NC2)* 3(NC3)* 4(NC4)* 5(NC5)* 6(NC6)* 7(NC7)* 8(NC8)* 9(NC9)* 10(NC10)* 11(NC11)* 12(NC12)* 13(NC13)* 14(NC14)* 19(NC15)* 20(NC16)* 21(NC17)* 22(NC18)* 23(NC(SW)1)* 37(NC19)* 38(NC20)* 49(NC(SW)2)* 50(NC(SW)3)* 51(NC(SW)4)* 52(NC(SW)5)* 53(NC21)* 54(NC22)* 55(NC23)* 56(NC24)*

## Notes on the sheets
sheet 38
- Power - S10 VCCRAM
- VCCRAM Sensing
- VCCRAM
- Remote
  Sense Near
  FPGA Power
  balls
- connect AGND to
  PGND through a
  single via
- H = 4.92mm
  Place on Top side
sheet 39
- Power - S10 VCCPT & 1.8V
- VCCPT Sensing
- VCCPT
- connect AGND to
  PGND through a
  single via
- H = 5.01mm
  Place on Top side
sheet 40
- Power - S10 VCCR_GXB, VCCT_GXB
- VCCT_GXB Current Sensing
- VCCR_GXB Current Sensing
- VCCT
- VCCR
- Route remote
  sense lines near
  the  FPGA Ball
- connect AGND to
  PGND through a
  single via
- H = 5.01mm
  Place on Top side
sheet 41
- Power - S10 VCCIO FMCA, FMCB
- VCCIO_FMCA Current Sensing
- FMCA
- S10 VCCIO_FMCA Variable
  1.2V, 1.35V, 1.5V, 1.8V
- H = 1.85mm
  Place on bottom side
- SS -> 22nF * 80kOhm = 1.76msec +/-25%
- VFB=0.75V
  IFB=5nA
- Resistor for LLM mode only.
  Open (DNI) for PWM mode.
- Default to internal pull-up on LLM
  to allow automatic engagement of
  Light Load Mode.
- Min (VIN - VOUT)  =  315mV for PWM
  Min (VIN - VOUT)  =  800mV for LLM
- connect AGND to
  PGND through a
  single via
- Install only one
- 1.35V
- 1.5V
- 1.8V
- FMCA Voltage
- Installed
- VCCIO FMCA SELECT
- NONE
- 1.2V
- R460
- 1.35V
- R464
- 1.5V
- R468
  (Default)
- 1.8V
sheet 42
- Power - HILO Memory
- HILO_VCCIO Current Sensing
- S10 HILO_VDD
  Variable 1.2V, 1.25V, 1.3V, 1.35V, 1.5V, 1.8V
- S10 HILO_VDDQ & VCCIO_HILO
  Variable 1.2V, 1.25V, 1.35V, 1.5V, 1.8V
- HILO VDD
- HILO VDDQ
- H = 3.00mm
  Place on Top side
- H = 3.00mm
  Place on Top side
- HILO  will GND the required SET pin to
  generate VDDQ voltage for memory interface.
  The default vaule is 1.2V.
- HILO  will GND the required SET pin to
  generate VDDQ voltage for memory interface.
  The default vaule is 1.2V.
- connect AGND to
  PGND through a
  single via
- connect AGND to
  PGND through a
  single via
